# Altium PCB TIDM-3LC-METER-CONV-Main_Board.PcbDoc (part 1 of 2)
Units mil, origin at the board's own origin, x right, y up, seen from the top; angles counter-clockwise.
Board outline 4050 x 4800 mil, 4 copper layers (Top Layer, Mid-Layer 1, Mid-Layer 2, Bottom Layer); 180 components, 206 nets, 819 pads, 257 vias.
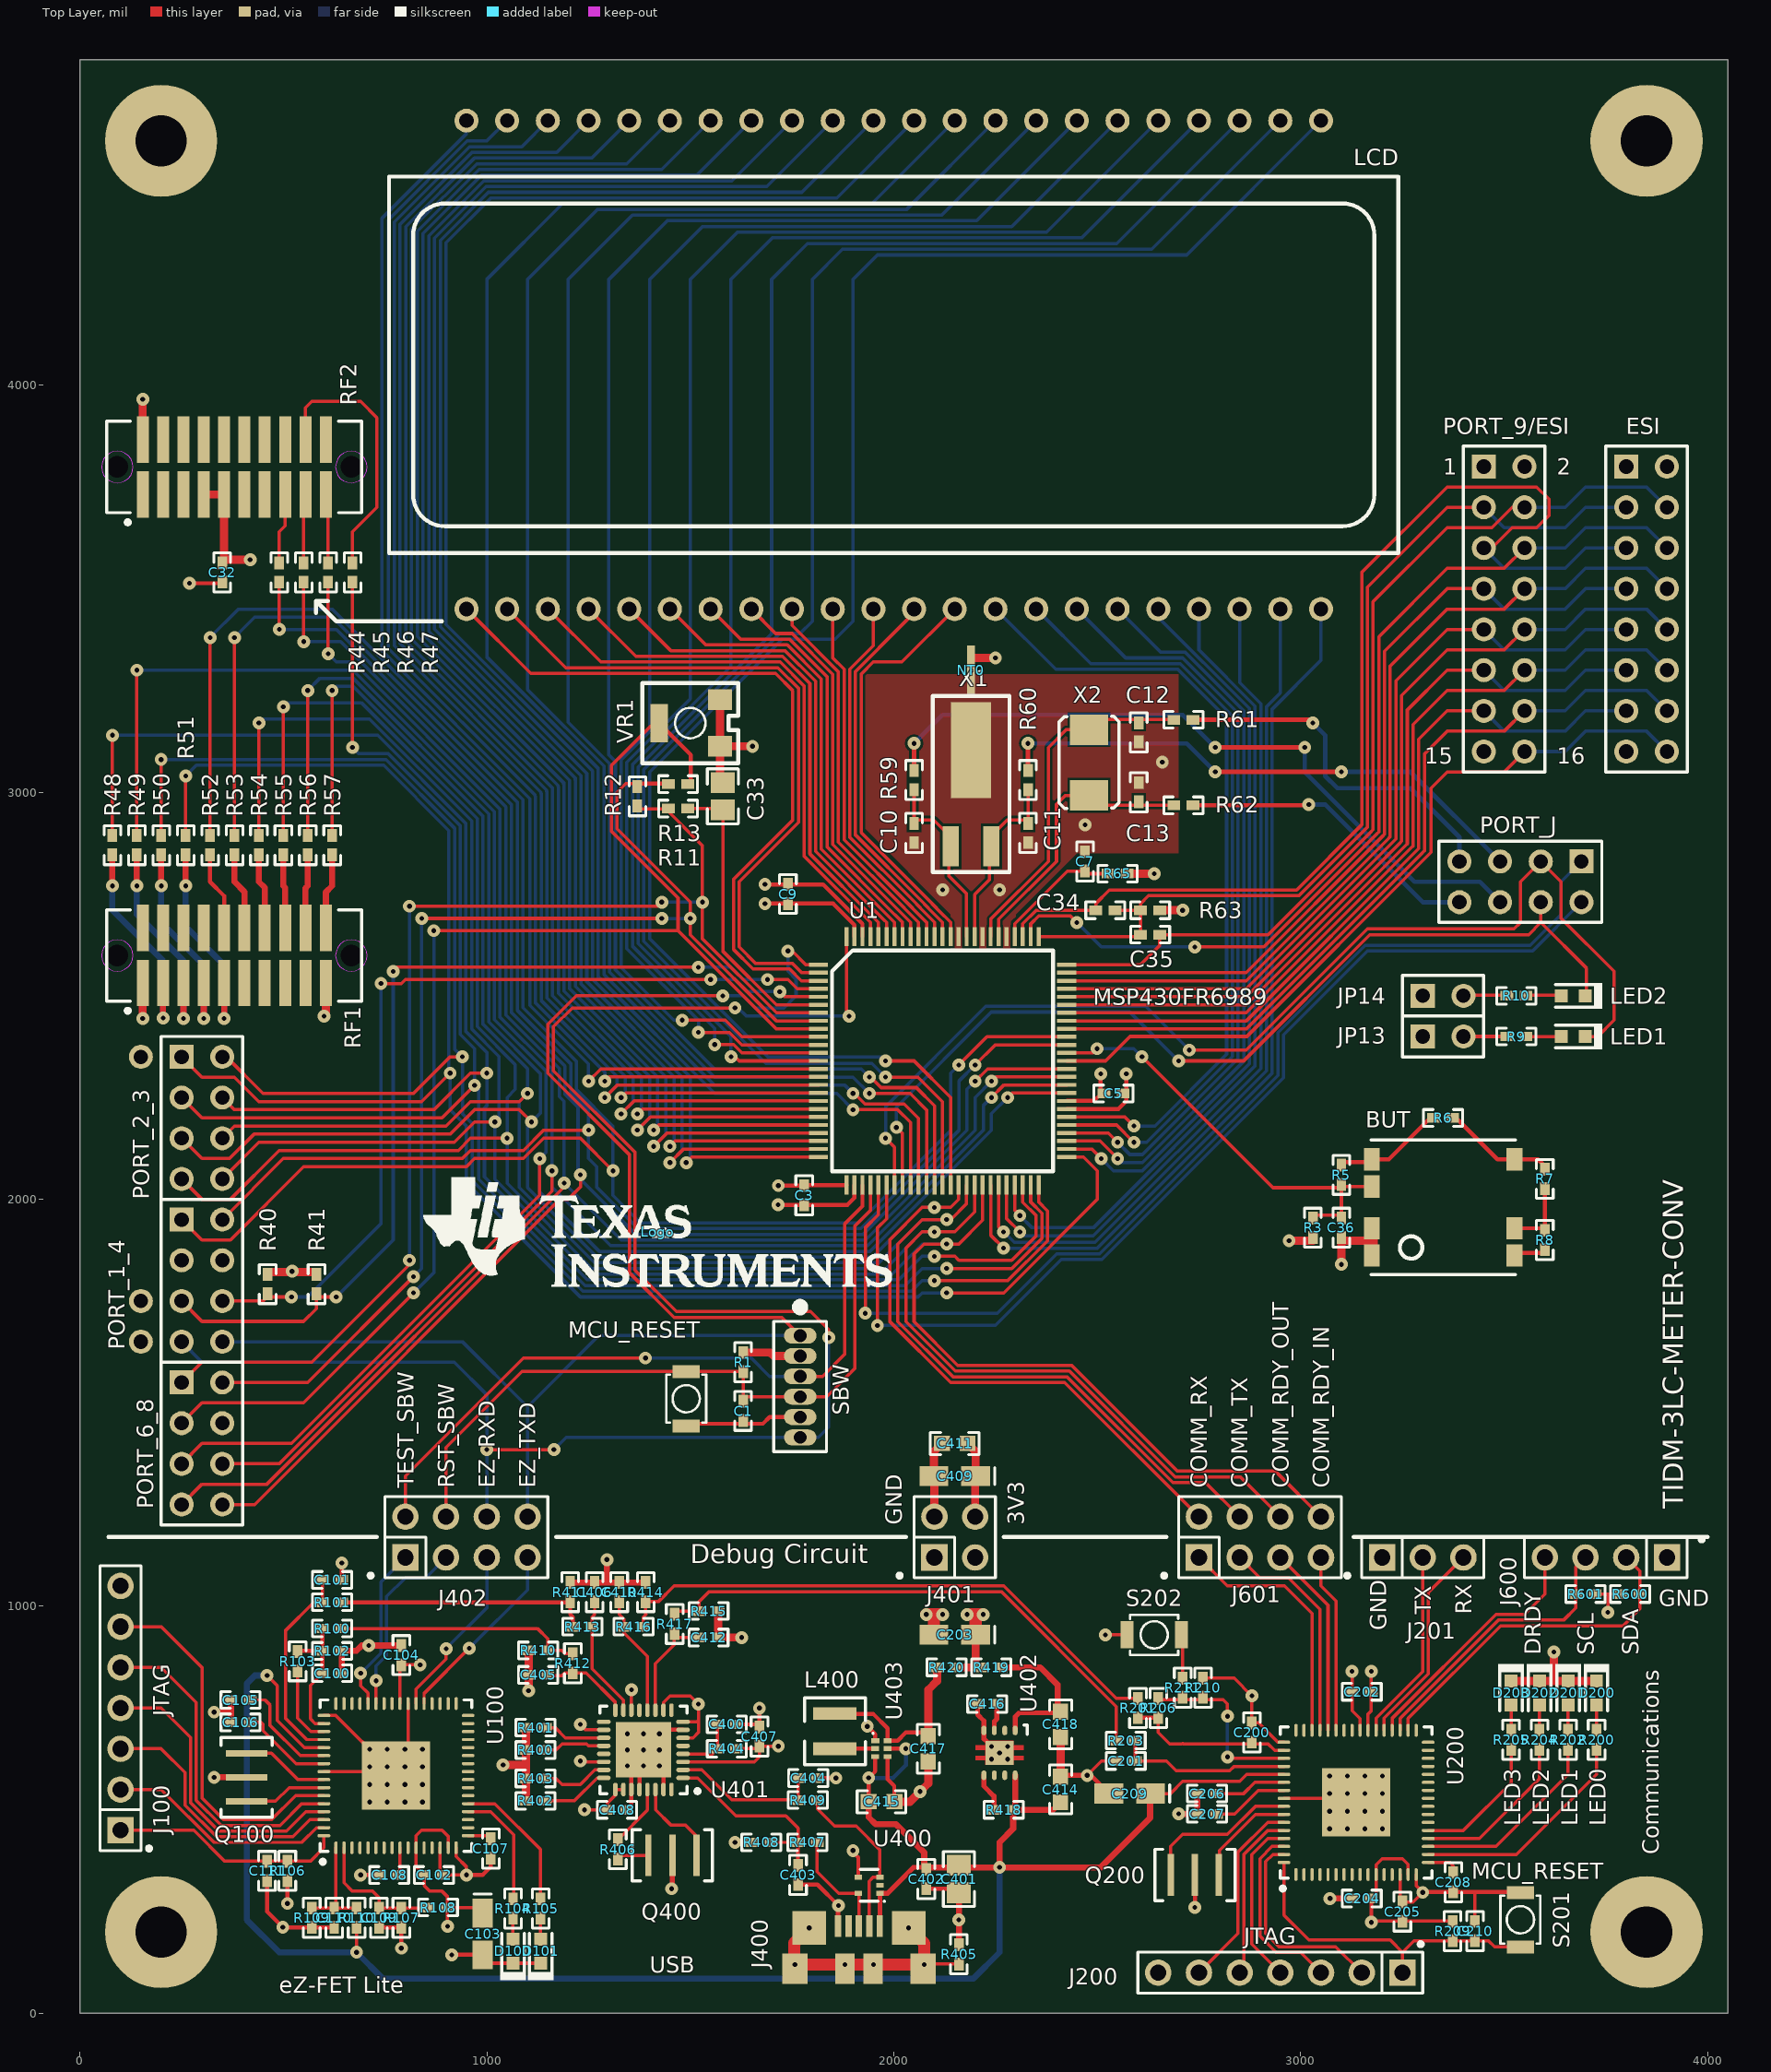
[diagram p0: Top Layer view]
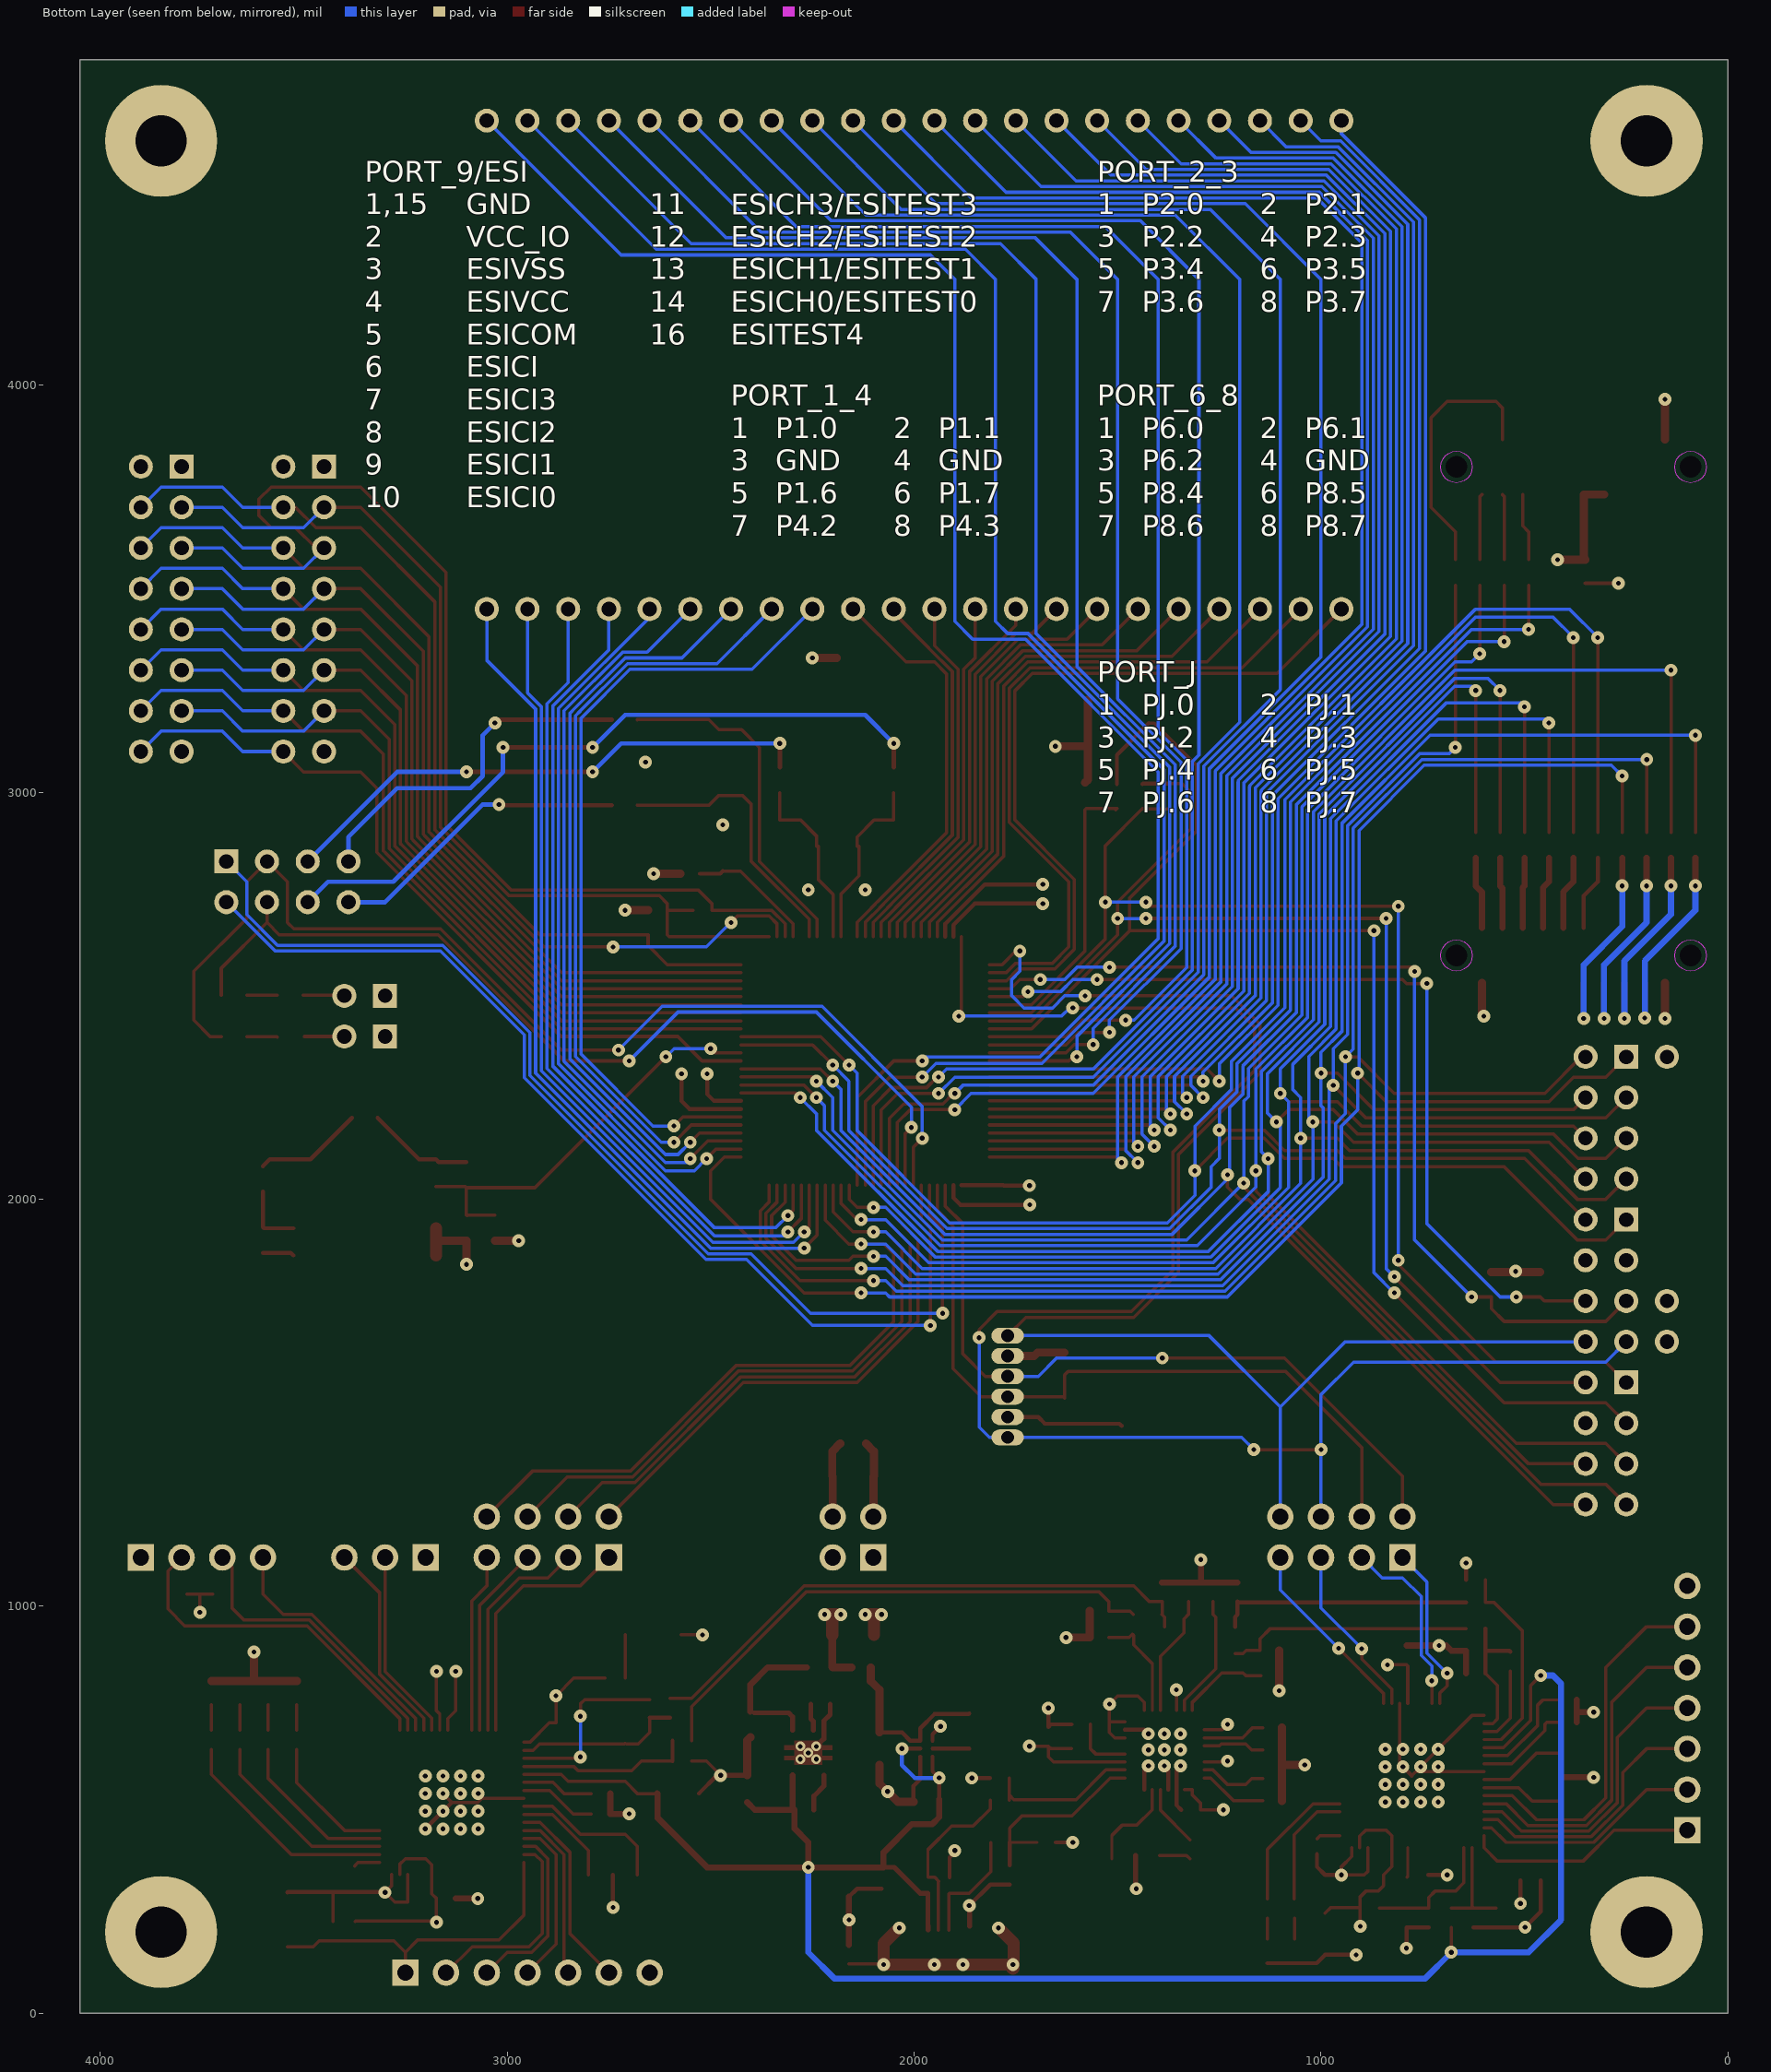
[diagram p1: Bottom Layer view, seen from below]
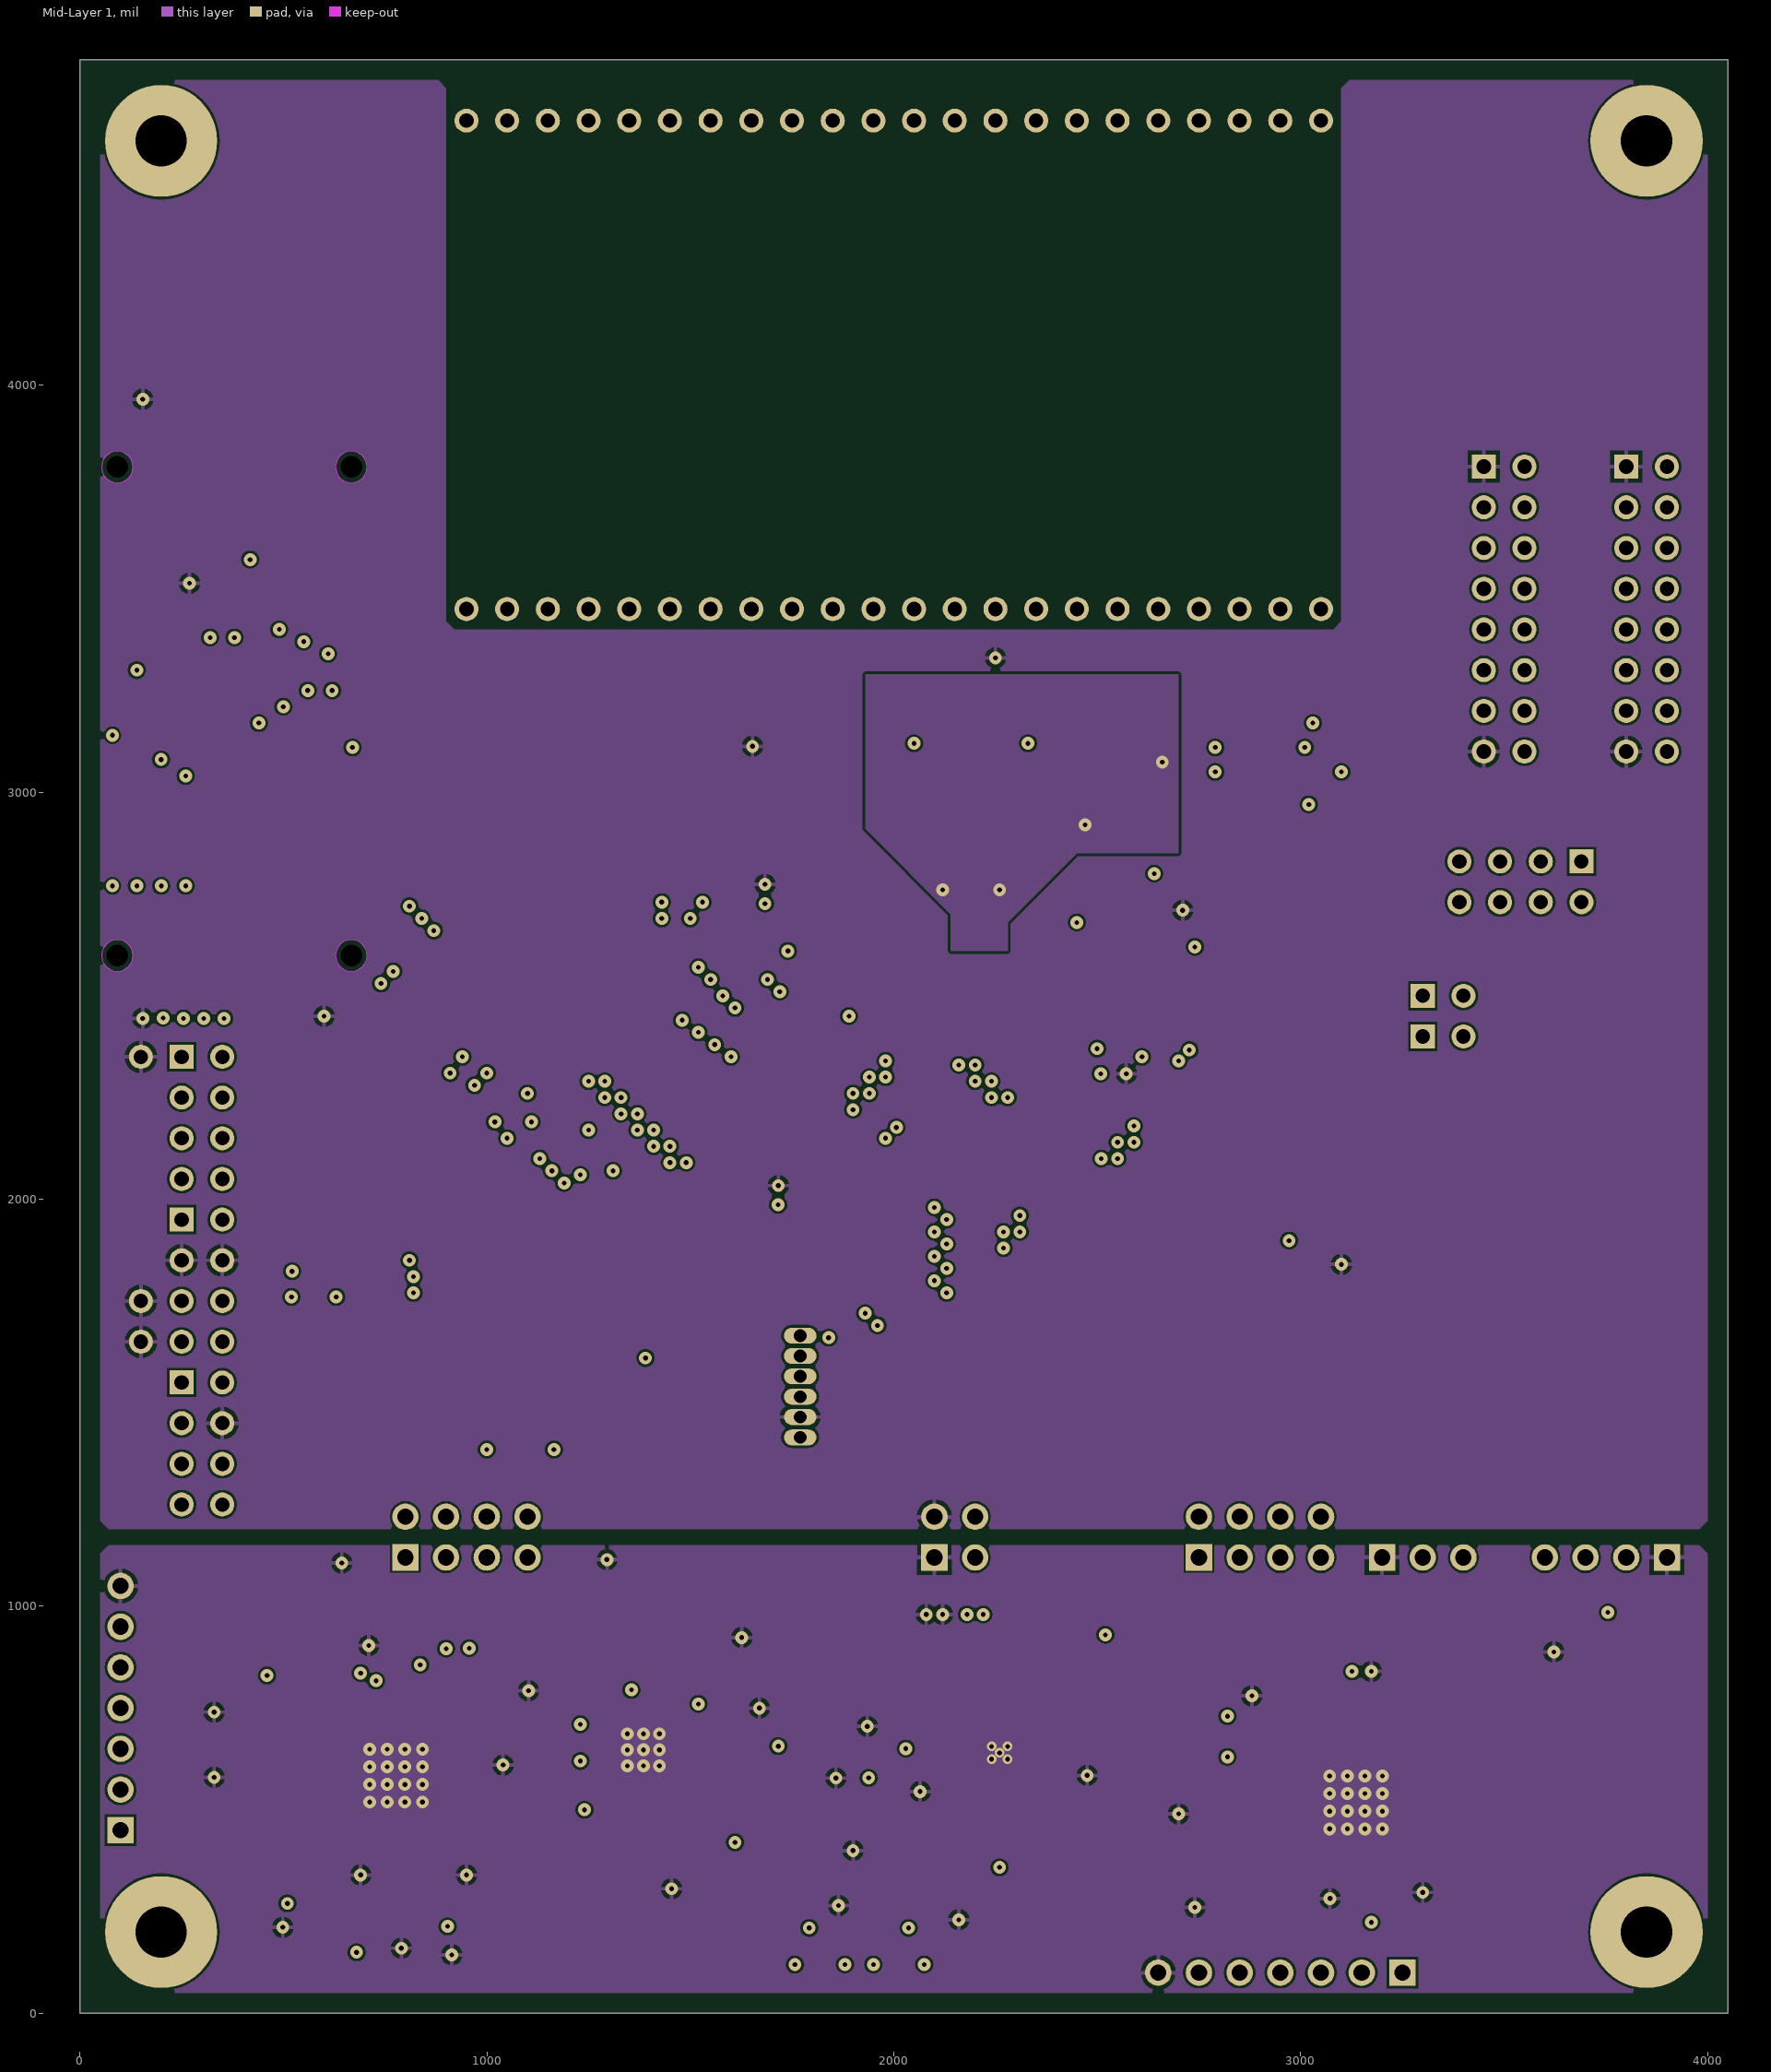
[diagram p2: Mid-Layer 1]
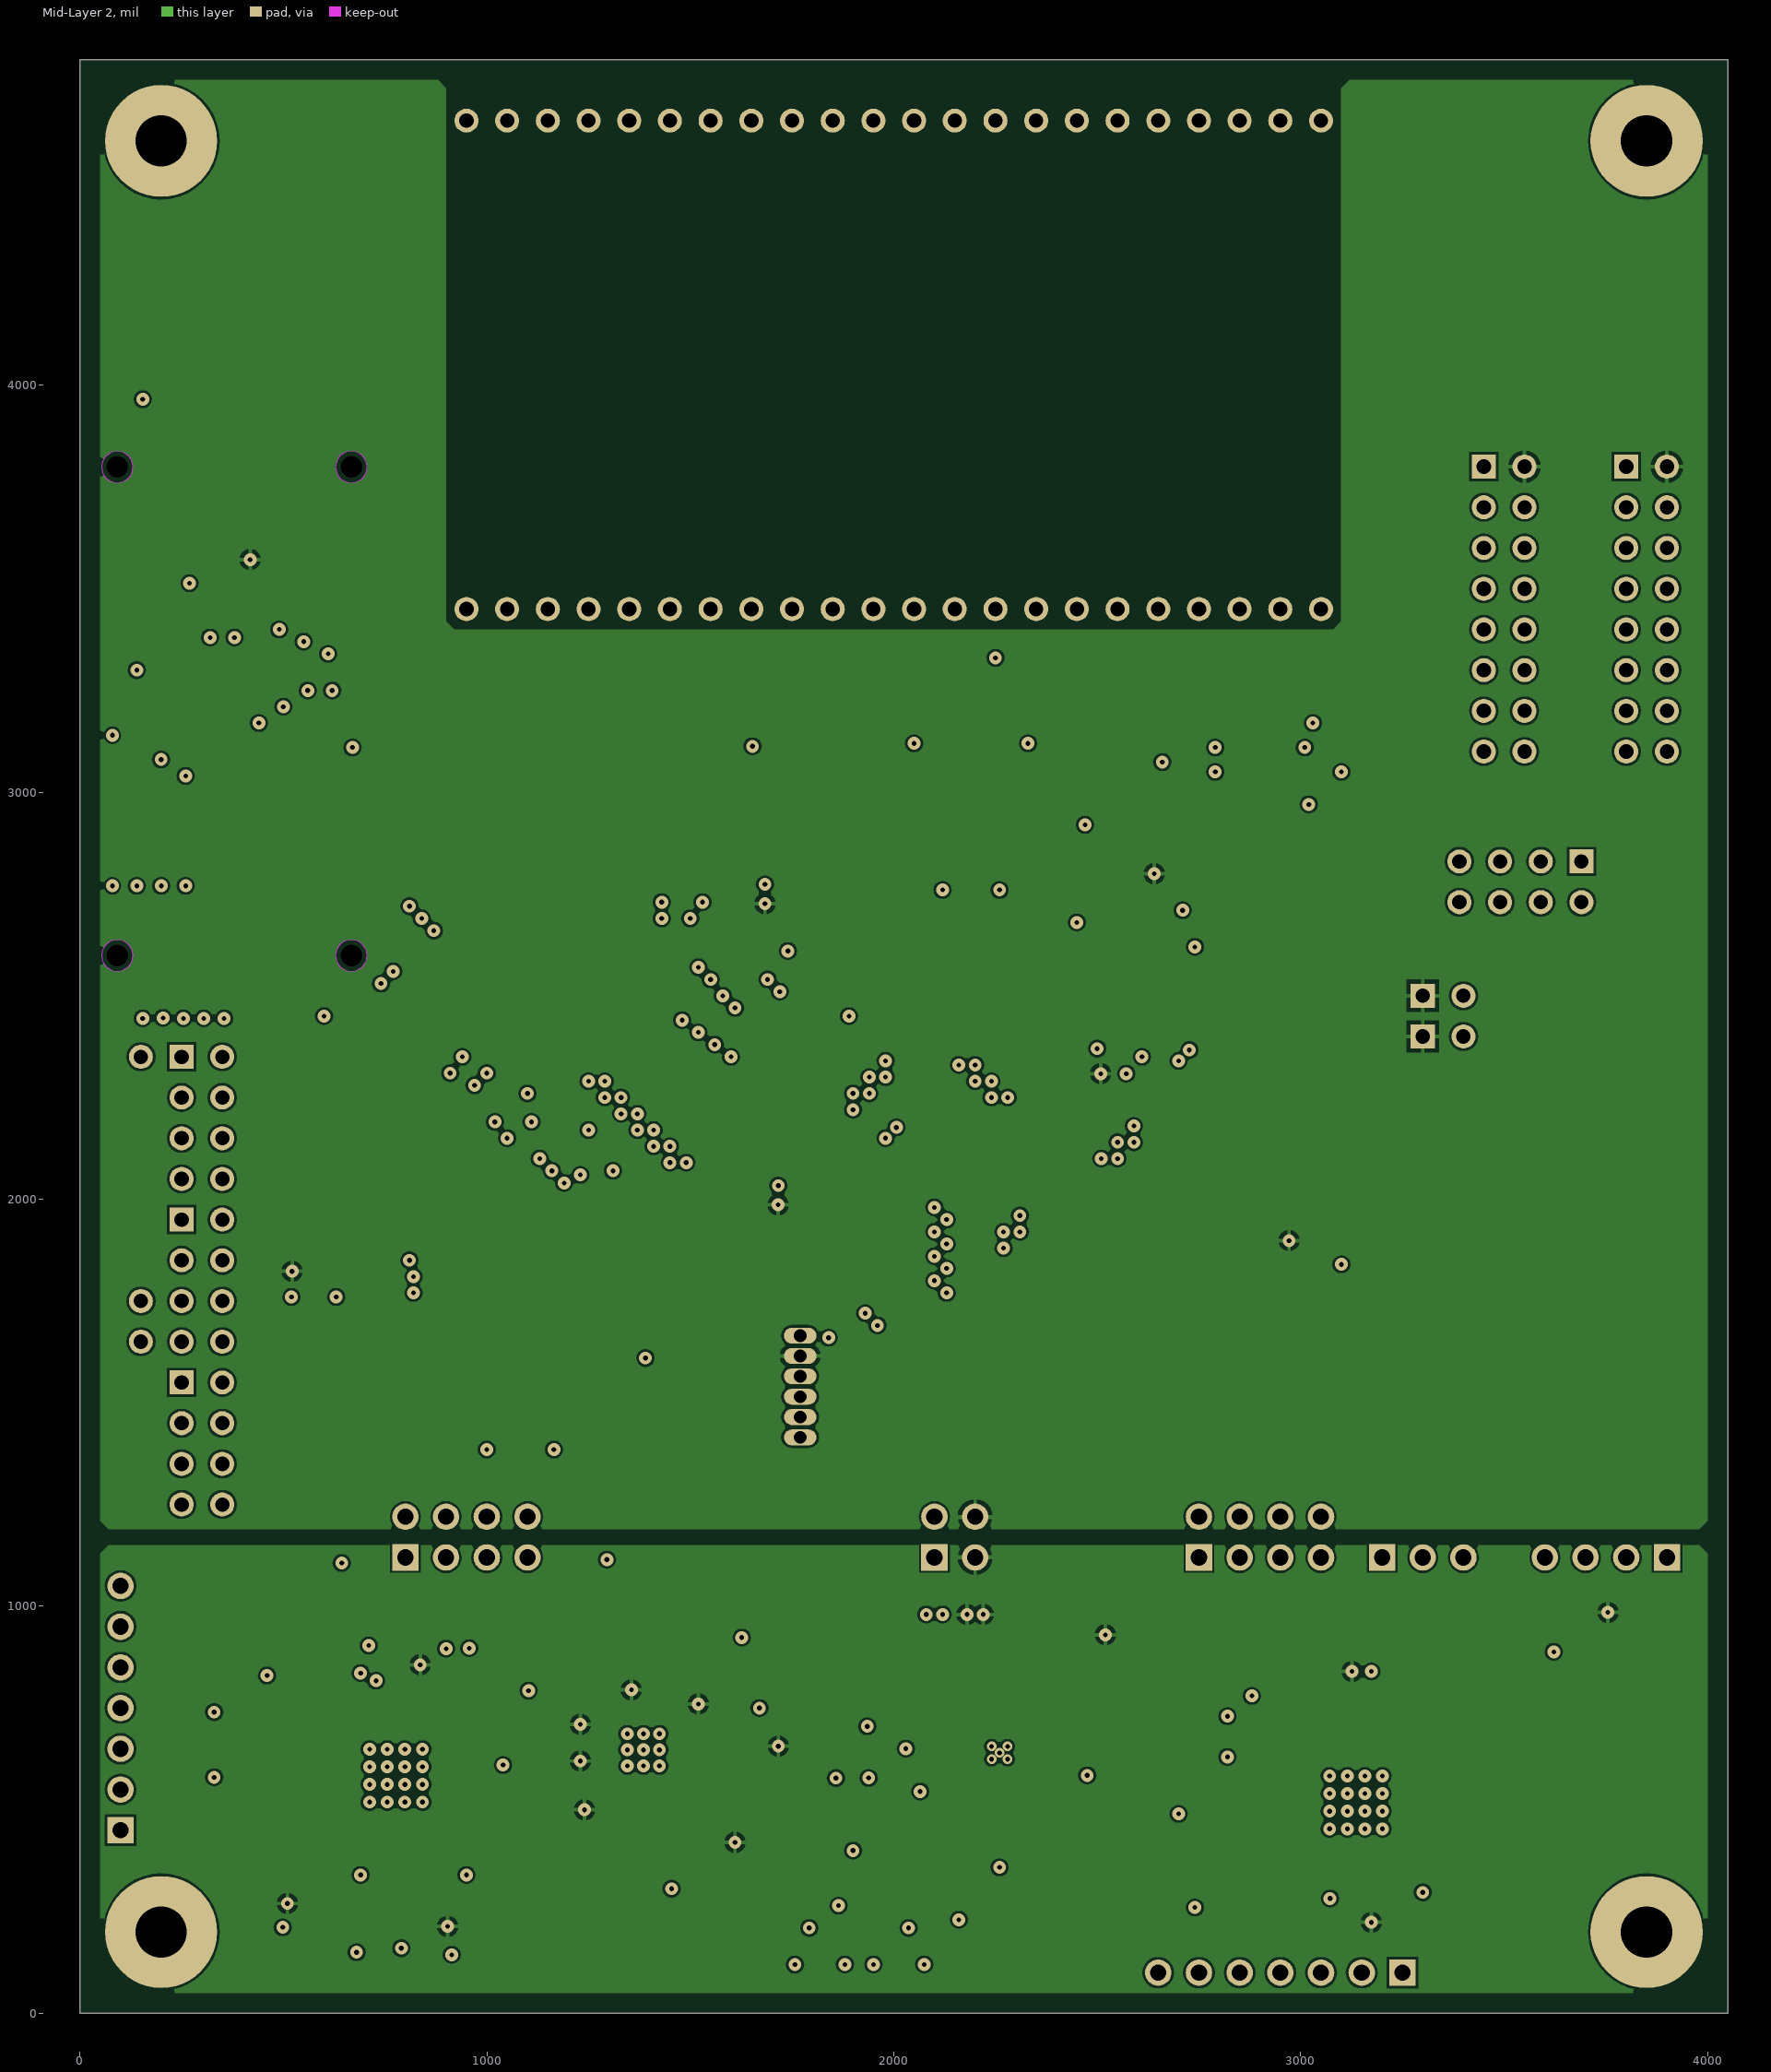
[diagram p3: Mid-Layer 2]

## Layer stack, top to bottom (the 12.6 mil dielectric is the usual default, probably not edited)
Top Layer: signal copper 1.4
Dielectric: core 12.6, FR-4, Dk 4.8
Mid-Layer 1: signal copper 1.4
Dielectric: prepreg 12.6, FR-4, Dk 4.8
Mid-Layer 2: signal copper 1.4
Dielectric: core 12.6, FR-4, Dk 4.8
Bottom Layer: signal copper 1.4

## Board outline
0,0 0,4800 4050,4800 4050,0

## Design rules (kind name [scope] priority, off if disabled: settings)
AcuteAngle [All] p1: minimum=4.50000000000000E+0001 checktracksonly=FALSE
AssemblyTestPointUsage [All] p1: valid=2
Clearance [All] p1: gap=6
Clearance Clearance_1 [InNet('AGND')] p2: gap=10
ComponentClearance ComponentClearance_Logo [All] p1 off: gap=50 collisioncheckmode=3 verticalgap=10 showdistances=FALSE
ComponentClearance ComponentClearance_ScrewToNut [(HasFootprint('NY PMS 440 0025 PH')) vs (HasFootprint('Keystone_1902C'))] p2 off: gap=5 collisioncheckmode=3 verticalgap=10 showdistances=FALSE
ComponentClearance ComponentClearance_MountingHoles [InComponentClass('Mounting Holes')] p3 off: gap=250 collisioncheckmode=3 verticalgap=100000 showdistances=FALSE
ComponentClearance ComponentClearance_SmallPassives [HasFootprint('0201*') or HasFootprint('0402*') or HasFootprint('0508') or HasFootprint('0603*') or HasFootprint('0612') or HasFootprint('0805*') or HasFootprint('0815*') or HasFootprint('0830*') or HasFootprint('1206*') or HasFootprint('1210*') or HasFootprint('1808*') or HasFootprint('1812*') or HasFootprint('1825*') or HasFootprint('2010*') or HasFootprint('2220*') or HasFootprint('2225*') or HasFootprint('2512*') or HasFootprint('2728*') or HasFootprint('3518*') vs HasFootprint('0201*') or HasFootprint('0402*') or HasFootprint('0508') or HasFootprint('0603*') or HasFootprint('0612') or HasFootprint('0805*') or HasFootprint('0815*') or HasFootprint('0830*') or HasFootprint('1206*') or HasFootprint('1210*') or HasFootprint('1808*') or HasFootprint('1812*') or HasFootprint('1825*') or HasFootprint('2010*') or HasFootprint('2220*') or HasFootprint('2225*') or HasFootprint('2512*') or HasFootprint('2728*') or HasFootprint('3518*')] p4 off: gap=20 collisioncheckmode=3 verticalgap=10 showdistances=FALSE
ComponentClearance ComponentClearance_THtoSMT [IsThruComponent vs IsSMTComponent] p5 off: gap=100 collisioncheckmode=3 verticalgap=100000 showdistances=FALSE
ComponentClearance ComponentClearance_THtoTH [IsThruComponent vs IsThruComponent] p6 off: gap=118.11 collisioncheckmode=3 verticalgap=100000 showdistances=FALSE
ComponentClearance [All] p7 off: gap=40 collisioncheckmode=3 verticalgap=10 showdistances=FALSE
DiffPairsRouting [All] p1: maxlimit=100 minlimit=10 mostfreqgap=10 maxuncoupledlength=1000
FabricationTestPointUsage TestPointUsage [All] p1: valid=2 allowmultiple=FALSE
FabricationTestpoint Testpoint [All] p1: side=3 testpointundercomponent=TRUE minsize=40 maxsize=100 preferedsize=60 minholesize=0 maxholesize=40 preferedholesize=32 testpointgrid=1 allowsidetop=TRUE allowsidebottom=TRUE usegrid=TRUE gridtolerance=0.01
FanoutControl Fanout_LCC [IsLCC] p1: bgadir=Out bgaviamode=Centered fanoutstyle=Auto fanoutdirection=Alternating viagrid=1 // Fanout_LCC (Default Rule)
FanoutControl Fanout_BGA [IsBGA] p2: bgadir=Out bgaviamode=Centered fanoutstyle=Auto fanoutdirection=Alternating viagrid=1 // Fanout_BGA (Default Rule)
FanoutControl Fanout_Default [All] p4: bgadir=Out bgaviamode=Centered fanoutstyle=Auto fanoutdirection=Alternating viagrid=1 // Fanout_Default (Default Rule)
FanoutControl Fanout_Small [(CompPinCount < 5)] p5: bgadir=Out bgaviamode=Centered fanoutstyle=Auto fanoutdirection=OutThenIn viagrid=1 // Fanout_Small (Default Rule)
HoleSize [All] p1: absolutevalues=TRUE maxlimit=248.03 minlimit=11.81 maxpercent=80.000 minpercent=20.000
MinimumAnnularRing [All] p1: minimumring=6
MinimumSolderMaskSliver MinimumSolderMaskSliver_Logo [InComponentClass('Logo') vs InComponentClass('Logo')] p1: minsoldermaskwidth=0.7
MinimumSolderMaskSliver [All] p2: minsoldermaskwidth=1
PlaneConnect PlaneConnect_1 [All] p1: planeconnectstyle=Relief reliefexpansion=10 reliefentries=4 reliefconductorwidth=10 reliefairgap=10
PolygonConnect PolygonConnect_5 [All vs IsNamedPolygon('Mid-Layer 1-No Net 4')] p1: connectstyle=Direct reliefconductorwidth=10 reliefentries=4 polygonreliefangle="90 Angle" airgapwidth=10
PolygonConnect PolygonConnect_4 [All vs IsNamedPolygon('Mid-Layer 1-No Net 3')] p2: connectstyle=Direct reliefconductorwidth=10 reliefentries=4 polygonreliefangle="90 Angle" airgapwidth=10
PolygonConnect PolygonConnect_3 [All vs IsNamedPolygon('Mid-Layer 1-No Net 2')] p3: connectstyle=Direct reliefconductorwidth=10 reliefentries=4 polygonreliefangle="90 Angle" airgapwidth=10
PolygonConnect PolygonConnect_2 [All vs IsNamedPolygon('Mid-Layer 1-No Net 1')] p4: connectstyle=Direct reliefconductorwidth=10 reliefentries=4 polygonreliefangle="90 Angle" airgapwidth=10
PolygonConnect [InNet('AGND')] p5: connectstyle=Direct reliefconductorwidth=10 reliefentries=4 polygonreliefangle="90 Angle" airgapwidth=10
PolygonConnect PolygonConnect_1 [All] p6: connectstyle=Relief reliefconductorwidth=10 reliefentries=4 polygonreliefangle="90 Angle" airgapwidth=10
RoutingVias [All] p1: holewidth=11.81 width=31.5 viastyle="Through Hole" minholewidth=11.81 minwidth=31.5 maxholewidth=31.5 maxwidth=59.06
SilkToSilkClearance [All] p1: silktosilkclearance=5
SilkscreenOverComponentPads [All] p1: minsilkscreentomaskgap=5
SolderMaskExpansion [All] p1: expansion=3
Width [All] p1: maxlimit=30 minlimit=6 preferedwidth=8
14 further rules are at their usual default settings.

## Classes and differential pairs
component class MCU: BUT C1 C3 C5 C7 C9 C10 C11 C12 C13 C32 C33 C34 C35 C36 ESI JP13 JP14 LCD LED1 LED2 LFXT Logo MCU_RESET NT0 PORT_1_4 PORT_2_3 PORT_6_8 PORT_9/ESI PORT_J R1 R3 R5 R6 R7 R8 R9 R10 R11 R12 R13 R40 R41 R44 R45 R46 R47 R48 R49 R50 R51 R52 R53 R54 R55 R56 R57 R59 R60 R61 R62 R63 R65 RF1 RF2 SBW U1 VR1 X1 X2
component class ezFET_lite_sch: C100 C101 C102 C103 C104 C105 C106 C107 C108 C109 C110 C111 C409 C411 D100 D101 J100 J401 J402 Q100 R100 R101 R102 R103 R104 R105 R106 R107 R108 R109 R110 U100
component class Header: J100 J200 J201 J401 J402 J600 J601
component class usb_hub_and_power_sch: C400 C401 C402 C403 C404 C405 C406 C407 C408 C410 C412 C414 C415 C416 C417 C418 J400 L400 Q400 R400 R401 R402 R403 R404 R405 R406 R407 R408 R409 R410 R411 R412 R413 R414 R415 R416 R417 R418 R419 R420 U400 U401 U402 U403
component class usb_mcu_bridge_sch: C200 C201 C202 C203 C204 C205 C206 C207 C208 C209 C210 D200 D201 D202 D203 J200 J201 J600 J601 Q200 R200 R201 R202 R203 R204 R205 R206 R209 R210 R211 R600 R601 S201 S202 U200
component class Logo: Logo

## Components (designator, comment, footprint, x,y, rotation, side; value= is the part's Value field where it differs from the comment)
BUT "Used in BOM report" TPA511GLFS 3350,1980 r0 top
C1 "" 0402 1630,1480 r90 top
C3 "" 0402 1780,2010 r270 top
C5 "" 0402 2540,2260 r0 top
C7 "" 0402 2470,2830 r270 top
C9 "" 0402 1740,2750 r270 top
C10 "" 0402 2050,2900 r90 top
C11 "" 0402 2330,2900 r270 top
C12 "" 0402 2602,3147 r90 top
C13 "" 0402 2602,3000 r90 top
C32 "" 0402 350,3540 r270 top
C33 "" 0805 1580,2990 r270 top
C34 "" 0402 2520,2710 r0 top
C35 "" 0402 2630,2650 r0 top
C36 "" 0402 3100,1930 r270 top
C100 "500R07S100JV4T" 0402 620,835.5 r0 top
C101 "500R07S100JV4T" 0402 620,1065 r0 top
C102 "C1005X5R1A104K" 0402 870,340 r0 top
C103 "TPSA106M010R1800" 3216-18 990,195 r270 top
C104 "C1005X5R1A104K" 0402 790,880 r90 top
C105 "GRM155R61A224KE19D" 0402 395,770 r180 top
C106 "GRM155R61A224KE19D" 0402 395,715 r180 top
C107 "GRM155R61A474KE15D" 0402 1010,405 r270 top
C108 "C1005X5R1A104K" 0402 760,340 r180 top
C109 "GRM1555C1H330JA01D" 0402 735,235 r270 top
C110 "GRM1555C1H330JA01D" 0402 625,235 r270 top
C111 "C1005X7R1H102K" 0402 460,350 r270 top
C200 "GRM1555C1H100JA01D" 0402 2880,690 r90 top
C201 "GRM1555C1H100JA01D" 0402 2570,620 r180 top
C202 "GRM155R61C104KA88D" 0402 3150,790 r0 top
C203 "TPSA106M010R1800" 3216-18 2150,930 r180 top
C204 "GRM155R61C104KA88D" 0402 3150,282.16 r180 top
C205 "GRM155R61C104KA88D" 0402 3250,250 r90 top
C206 "GRM155R61A224KE19D" 0402 2770,540 r180 top
C207 "GRM155R61A224KE19D" 0402 2770,490 r180 top
C208 "GRM155R61A474KE15D" 0402 3375,322.16 r270 top
C209 "293D106X0010A2TE3" 3216-18 2580,540 r180 top
C210 "C1005X7R1H102K" 0402 3428.19,202.16 r90 top
C400 "GRM155R61C104KA88D" 0402 1590,710 r0 top
C401 "293D475X9010A2TE3" 0805 2160,330 r270 top
C402 "GRM155R61C104KA88D" 0402 2080,330 r270 top
C403 "GRM1555C1H220JA01D" 0402 1765,340 r270 top
C404 "GRM1555C1H220JA01D" 0402 1790,578 r0 top
C405 "GRM1555C1H100JA01D" 0402 1126.31,831.65 r180 top
C406 "GRM1555C1H100JA01D" 0402 1265,1035 r90 top
C407 "GRM155R61C104KA88D" 0402 1670,680 r90 top
C408 "GRM155R61C104KA88D" 0402 1320,500 r0 top
C409 "TPSA106M010R1800" 3216-18 2150,1320 r180 top
C410 "GRM1555C1H100JA01D" 0402 1325.5,1035 r90 top
C411 "C1608X7R1C105K" 0603 2150,1400 r180 top
C412 "GRM1555C1H100JA01D" 0402 1545,923.35 r0 top
C414 "C0603C105K8PACTU" 0603 2410,550 r90 top
C415 "GRM21BR71A105KA01L" 0603 1970,520 r0 top
C416 "GRM155R61C103KA01D" 0402 2230,760 r180 top
C417 "GRM21BR71A105KA01L" 0603 2085,650 r270 top
C418 "C0603C225K8PACTU" 0603 2410,710 r270 top
D100 "LTST-C190CKT" LED_LTST-C190_Red 1064.44,152.69 r270 top
D101 "LTST-C190GKT" LED_LTST-C190 1132.16,152.69 r270 top
D200 "LTST-C190CKT" LED_LTST-C190_Red 3727,787.16 r90 top
D201 "LTST-C190GKT" LED_LTST-C190 3657,787.16 r90 top
D202 "LTST-C190GKT" LED_LTST-C190 3587,787.16 r90 top
D203 "LTST-C190GKT" LED_LTST-C190 3517,787.16 r90 top
ESI "MHDR2X8" HDR2X8 3800,3800 r270 top
J100 "TSW-107-07-G-S" TSW-107-07-G-S 100,750 r90 top
J200 "TSW-107-07-G-S" TSW-107-07-G-S 2950,100 r180 top
J201 "TSW-103-07-G-S" TSW-103-07-G-S 3300,1120 r0 top
J400 "ZX62R-B-5P" CONN_USB_micro_ZX62R-B-5PA 1914.45,214.68 r0 top
J401 "TSW-102-07-G-D" TSW-102-07-G-D 2150,1170 r0 top
J402 "TSW-104-07-G-D" TSW-104-07-G-D 950,1170 r0 top
J600 "TSW-104-07-G-S" TSW-104-07-G-S 3750,1120 r180 top
J601 "TSW-104-07-G-D" TSW-104-07-G-D 2900,1170 r0 top
JP13 "JUMPER" HDR1X2 3300,2400 r0 top
JP14 "JUMPER" HDR1X2 3300,2500 r0 top
L400 "NR3010T2R2M" INDUCTOR_2.2UH_SMD 1855,650 r90 top
LCD "FH-1152P" FH-1152P 2000,4050 r0 top locked
LED1 "" LED_LTST-C190 3670,2400 r0 top
LED2 "" LED_LTST-C190 3670,2500 r0 top
Logo "Texas Instruments" TI_Stacked_Overlay_Medium 1420,1920 r0 top
MCU_RESET "" B3U-1000P 1490,1510 r90 top
NT0 "Net-Tie" Net-Tie_20milWide_60milLong 2190,3300 r90 top net-tie
PORT_1_4 "MHDR2X4" HDR2X4 250,1950 r270 top
PORT_2_3 "MHDR2X4" HDR2X4 250,2350 r270 top
PORT_6_8 "MHDR2X4" HDR2X4 250,1550 r270 top
PORT_9/ESI "MHDR2X8" HDR2X8 3450,3800 r270 top (schematic designator ESI2)
PORT_J "MHDR2X4" HDR2X4 3690,2830 r180 top
Q100 "MURATA-FILTER_CSTCR4M00G15" "CSTCR CERAMIC RESONATOR - MURATA" 410,580 r270 top
Q200 "MURATA-FILTER_CSTCR4M00G15" "CSTCR CERAMIC RESONATOR - MURATA" 2740,340 r0 top
Q400 "CSTCR4M00G15L99" "CSTCR CERAMIC RESONATOR - MURATA" 1456,388 r180 top
R1 "" 0402 1630,1600 r90 top
R3 "" 0402 3030,1930 r270 top
R5 "" 0402 3100,2060 r270 top
R6 "" 0402 3350,2200 r180 top
R7 "" 0402 3600,2050 r90 top
R8 "" 0402 3600,1900 r90 top
R9 "" 0402 3530,2400 r0 top
R10 "" 0402 3530,2500 r0 top
R11 "" 0402 1470,2960 r0 top
R12 "" 0402 1370,2990 r270 top
R13 "" 0402 1470,3020 r180 top
R40 "" 0402 461.49,1791.49 r90 top
R41 "" 0402 581.49,1791.49 r90 top
R44 "" 0402 490,3540 r270 top
R45 "" 0402 550,3540 r270 top
R46 "" 0402 610,3540 r270 top
R47 "" 0402 670,3540 r270 top
R48 "" 0402 80,2870 r90 top
R49 "" 0402 140,2870 r90 top
R50 "" 0402 200,2870 r90 top
R51 "" 0402 260,2870 r90 top
R52 "" 0402 320,2870 r90 top
R53 "" 0402 380,2870 r90 top
R54 "" 0402 440,2870 r90 top
R55 "" 0402 500,2870 r90 top
R56 "" 0402 560,2870 r90 top
R57 "" 0402 620,2870 r90 top
R59 "" 0402 2050,3030 r90 top
R60 "" 0402 2330,3030 r90 top
R61 "" 0402 2712,3178 r180 top
R62 "" 0402 2712,2968 r180 top
R63 "" 0402 2630,2710 r180 top
R65 "" 0402 2550,2800 r0 top
R100 "CRCW040227R0JNED" 0402 620,945.5 r180 top
R101 "CRCW040227R0JNED" 0402 620,1010 r180 top
R102 "CRCW04021M00JNED" 0402 620,890.5 r0 top
R103 "CRCW04021K30JNED" 0402 535,865 r90 top
R104 "CRCW0402470RJNED" 0402 1064.44,257.69 r90 top
R105 "CRCW0402390RJNED" 0402 1132.16,257.69 r90 top
R106 "CRCW040247K0JNED" 0402 510,350 r270 top
R107 "CRCW0402220KJNED" 0402 790,235 r90 top
R108 "CRCW0402220KJNED" 0402 880,260 r0 top
R109 "CRCW0402150KFKED" 0402 570,235 r90 top
R110 "CRCW0402240KJNED" 0402 680,235 r270 top
R200 "CRCW0402470RJNED" 0402 3727,672.16 r270 top
R201 "CRCW040227R0JNED" 0402 2600,750 r270 top
R202 "CRCW0402390RJNED" 0402 3657,672.16 r270 top
R203 "CRCW040227R0JNED" 0402 2570,670 r0 top
R204 "CRCW0402390RJNED" 0402 3587,672.16 r270 top
R205 "CRCW0402390RJNED" 0402 3517,672.16 r270 top
R206 "CRCW04021K40FKED" 0402 2650,750 r90 top
R209 "CRCW040247K0JNED" 0402 3373.19,202.16 r90 top
R210 "CRCW04021M00JNED" 0402 2760,800 r270 top
R211 "CRCW0402100RJNED" 0402 2710,800 r90 top
R400 "CRCW040215K0FKED" 0402 1119.84,646.97 r0 top
R401 "CRCW040215K0FKED" 0402 1119.84,701.97 r0 top
R402 "CRCW040215K0FKED" 0402 1119.84,521.97 r0 top
R403 "CRCW040215K0FKED" 0402 1119.84,576.97 r0 top
R404 "CRCW040247K0JNED" 0402 1590,650 r0 top
R405 "CRCW040233R0JNED" 0402 2160,145 r90 top
R406 "CRCW040227R0JNED" 0402 1322,403 r90 top
R407 "CRCW040222R0JNED" 0402 1788.19,420 r180 top
R408 "CRCW04021K50JNED" 0402 1675,420 r180 top
R409 "CRCW040222R0JNED" 0402 1789.19,524 r180 top
R410 "CRCW040215K0FKED" 0402 1126.31,891.65 r0 top
R411 "CRCW040215K0FKED" 0402 1205,1035 r270 top
R412 "CRCW040222R0JNED" 0402 1211.31,860 r270 top
R413 "CRCW040222R0JNED" 0402 1235,950 r0 top
R414 "CRCW040215K0FKED" 0402 1390.5,1035 r270 top
R415 "CRCW040215K0FKED" 0402 1545,988.35 r180 top
R416 "CRCW040222R0JNED" 0402 1360.5,950 r180 top
R417 "CRCW040222R0JNED" 0402 1461.65,956.81 r270 top
R418 "CRCW040210K0JNED" 0402 2270,500 r180 top
R419 "CRCW040222R0JNED" 0402 2240,850 r0 top
R420 "CRCW040222R0JNED" 0402 2130,850 r180 top
R600 "CRCW04024K70JNED" 0402 3810,1030 r0 top
R601 "CRCW04024K70JNED" 0402 3700,1030 r180 top
RF1 "MHDR2X10" TFM-110-02-SM-D-A-K 379.5,2599 r0 top
RF2 "MHDR2X10" TFM-110-02-SM-D-A-K 379.5,3799 r0 top locked
S201 "" B3U-1000P 3540,230 r270 top
S202 "" B3U-1000P 2640,930 r180 top
SBW "Header 6" CONN_SMS-106-01-G-S 1770,1540 r90 top
U1 "MSP430FR6989" MSP430FR6989 2120,2340 r270 top
U100 "MSP430F5528IRGCR" TI_RGC0064B_N 777,584 r90 top
U200 "MSP430F5528IRGCT" TI_RGC0064B_N 3136.08,518.24 r90 top
U400 "TPD2E001DRLR" DRL0005A 1939.45,314.68 r180 top
U401 "TUSB2046BIRHBR" RHB0032E 1384.84,647.28 r180 top
U402 "TPS73533DRB (DNP)" DRB0008A 2260,640 r270 top
U403 "TPS62237DRYR" DRY0006A 1969.84,650.32 r0 top
VR1 "" VR-3150 1500,3170 r90 top
X1 "32.768" 01-CR3-1B 2190,3020 r270 top
X2 "DNP" ABM3 2480,3073 r90 top

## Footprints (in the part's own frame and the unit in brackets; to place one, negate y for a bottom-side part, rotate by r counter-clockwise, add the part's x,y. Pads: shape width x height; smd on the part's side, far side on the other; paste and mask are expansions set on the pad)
01-CR3-1B [mm]
  rect 2.5x1 smd: 1(3.875,-1.27) 2(3.875,1.27)
  rect 6x2.5 smd: 3(-2.125,0)
  silkscreen extent -5.5,-2.4 5.5,2.4
0402 [mm] "0402 from SM-752 data"
  rect 0.8x0.6 smd: 1(-0.6,0) 2(0.6,0)
  silkscreen extent -1.22,-0.52 1.22,0.52, body extent -0.55,-0.3 0.55,0.3, height 0.6
0603 [mm] "0603 from SM-752 data"
  rect 1x0.95 smd: 1(-0.8,0) 2(0.8,0)
  silkscreen extent -1.52,-0.69 1.52,0.69, body extent -0.87,-0.47 0.87,0.47, height 0.85
0805 [mm] "0805 from SM-752 data"
  rect 1.3x1.5 smd: 1(-0.85,0) 2(0.85,0)
  silkscreen extent -1.72,-0.97 1.72,0.97, body extent -1.1,-0.72 1.1,0.72, height 1.1
3216-18 [mm] "Medium density IPC, based on Kemet T495 dimensions"
  rect 1.8x1.25 smd: 1(-1.3,0) 2(1.3,0)
  silkscreen extent -2.49,-0.54 -2.49,0.54, body extent -1.7,-0.9 1.7,0.9, height 1.8
ABM3 [mm]
  rect 1.9x2.4 smd: 1(2.05,0) 2(-2.05,0)
  silkscreen extent -2.86,-1.87 2.89,1.87
B3U-1000P [mm]
  rect 0.8x1.7 smd: 1(-1.7,0) 2(1.7,0)
  silkscreen extent -1.5,-1.25 1.5,1.25
CONN_SMS-106-01-G-S [mil] "SAMTEC"
  oval 39x80 hole 31 mask+3: 1(125,0) 2(75,0) 3(25,0) 4(-25,0) 5(-75,0) 6(-125,0)
  silkscreen extent -160,-65 205,65, body extent -158,-62 158,62, height 341
CONN_USB_micro_ZX62R-B-5PA [mm] "Hirose"
  rect 0.4x1.35 smd: 1(1.3,0) 2(0.65,0) 3(0,0) 4(-0.65,0) 5(-1.3,0)
  rect 1.2x1.9 smd: 6(-0.875,-2.675) 7(0.875,-2.675)
  rect 1.6x1.9 smd: 8(-4,-2.675) 9(4,-2.675)
  rect 2.1x2.1 smd: 10(-3.1,-0.125) 11(3.1,-0.125)
  body extent -3.75,-5.33 3.75,0.18, height 2.55
"CSTCR CERAMIC RESONATOR - MURATA" [mm] "CSTCR-Resonator SMD footprint"
  rect 0.4x2.6 smd: 1(-1.5,0) 2(0,0) 3(1.5,0)
  silkscreen extent -2.49,-1.6 2.5,1.6, body extent -2.25,-1 2.25,1, height 1.1
DRB0008A [mm] "SON, 8-Leads, Body 3x3mm, Pitch 0.65mm, Thermal Pad 1.75x1.5mm, TI Recommended"
  oval 0.6x0.3 smd: 1(-1.4,0.975) 2(-1.4,0.325) 3(-1.4,-0.325) 4(-1.4,-0.975) 5(1.4,-0.975) 6(1.4,-0.325) 7(1.4,0.325) 8(1.4,0.975)
  rect 1.5x1.75 smd paste-0.75: 9(0,0)
  Top Layer region: -0.465,-1.5 -0.465,-0.875 -0.75,-0.875 -0.75,0.875 -0.465,0.875 -0.465,1.5 -0.185,1.5 -0.185,0.875 0.185,0.875 0.185,1.5 0.465,1.5 0.465,0.875 0.75,0.875 0.75,-0.875 0.465,-0.875 0.465,-1.5 0.185,-1.5 0.185,-0.875 -0.185,-0.875 -0.185,-1.5
  silkscreen extent -1.72,1.53 -1.15,1.73, body extent -1.57,-1.57 1.58,1.58, height 1.01
DRL0005A [mm] "SOTFL, 5-Flat Leads, Body 1.2x1.6x0.6mm, Pitch 0.5mm, TI Recommended"
  rect 0.45x0.3 smd: 1(-0.675,0.5) 2(-0.675,0) 3(-0.675,-0.5) 4(0.675,-0.5) 5(0.675,0.5)
  silkscreen extent -1,-1 0.55,1.05, body extent -0.65,-0.85 0.65,0.85, height 0.6
DRY0006A [mm] "PSON, 6-Leads, Body 1x1.45mm, Pitch 0.5mm, TI Recommended"
  rect 0.52x0.3 smd paste+0 mask+0.05: 1(-0.385,0.5)
  rect 0.49x0.3 smd paste+0 mask+0.05: 2(-0.385,0) 3(-0.385,-0.5) 4(0.385,-0.5) 5(0.385,0) 6(0.385,0.5)
  silkscreen extent -0.57,0.9 -0.48,1, body extent -0.53,-0.75 0.53,0.75, height 0.6
FH-1152P [mm]
  round 1.5 hole 0.9: 1(-26.67,-15.24) 2(-24.13,-15.24) 3(-21.59,-15.24) 4(-19.05,-15.24) 5(-16.51,-15.24) 6(-13.97,-15.24) 7(-11.43,-15.24) 8(-8.89,-15.24) 9(-6.35,-15.24) 10(-3.81,-15.24) 11(-1.27,-15.24) 12(1.27,-15.24) 13(3.81,-15.24) 14(6.35,-15.24) 15(8.89,-15.24) 16(11.43,-15.24) 17(13.97,-15.24) 18(16.51,-15.24) 19(19.05,-15.24) 20(21.59,-15.24) 21(24.13,-15.24) 22(26.67,-15.24) 23(26.67,15.24) 24(24.13,15.24) 25(21.59,15.24) 26(19.05,15.24) 27(16.51,15.24) 28(13.97,15.24) 29(11.43,15.24) 30(8.89,15.24) 31(6.35,15.24) 32(3.81,15.24) 33(1.27,15.24) 34(-1.27,15.24) 35(-3.81,15.24) 36(-6.35,15.24) 37(-8.89,15.24) 38(-11.43,15.24) 39(-13.97,15.24) 40(-16.51,15.24) 41(-19.05,15.24) 42(-21.59,15.24) 43(-24.13,15.24) 44(-26.67,15.24)
  silkscreen extent -31.5,-11.75 31.5,11.75
HDR1X2 [mm] "Connector; Header; 2 Position"
  rect 1.5x1.5 hole 0.9: 1(0,0)
  round 1.5 hole 0.9: 2(2.54,0)
  silkscreen extent -1.27,-1.27 3.81,1.27
HDR2X4 [mm] "Connector; Header; 4x2 Position"
  rect 1.5x1.5 hole 0.9: 1(0,0)
  round 1.5 hole 0.9: 2(0,2.54) 3(2.54,0) 4(2.54,2.54) 5(5.08,0) 6(5.08,2.54) 7(7.62,0) 8(7.62,2.54)
  silkscreen extent -1.27,-1.27 8.89,3.81
HDR2X8 [mm] "Connector; Header; 8x2 Position"
  rect 1.5x1.5 hole 0.9: 1(0,0)
  round 1.5 hole 0.9: 2(0,2.54) 3(2.54,0) 4(2.54,2.54) 5(5.08,0) 6(5.08,2.54) 7(7.62,0) 8(7.62,2.54) 9(10.16,0) 10(10.16,2.54) 11(12.7,0) 12(12.7,2.54) 13(15.24,0) 14(15.24,2.54) 15(17.78,0) 16(17.78,2.54)
  silkscreen extent -1.27,-1.27 19.05,3.81
INDUCTOR_2.2UH_SMD [mm] "Inductor, 2.2uH, 1A, 3x3mm, SMD footprint"
  rect 0.8x2.7 smd: 1(0,0) 2(2.2,0)
  silkscreen extent -0.99,-1.91 3.17,1.88, body extent -0.65,-1.6 2.85,1.6, height 1
LED_LTST-C190 [mm] "Lite-On"
  rect 0.8x0.8 smd: 1(-0.75,0) 2(0.75,0)
  silkscreen extent -1.1,-0.8 1.8,0.8, body extent -0.85,-0.45 0.85,0.45, height 0.9
LED_LTST-C190_Red [mm] "Lite-On"
  rect 0.8x0.8 smd: 1(-0.75,0) 2(0.75,0)
  silkscreen extent -1.1,-0.8 1.8,0.8, body extent -0.85,-0.45 0.85,0.45, height 0.9
MSP430FR6989 [mm]
  rect 0.25x1.2 smd: 1(-6,-7.75) 2(-5.5,-7.75) 3(-5,-7.75) 4(-4.5,-7.75) 5(-4,-7.75) 6(-3.5,-7.75) 7(-3,-7.75) 8(-2.5,-7.75) 9(-2,-7.75) 10(-1.5,-7.75) 11(-1,-7.75) 12(-0.5,-7.75) 13(0,-7.75) 14(0.5,-7.75) 15(1,-7.75) 16(1.5,-7.75) 17(2,-7.75) 18(2.5,-7.75) 19(3,-7.75) 20(3.5,-7.75) 21(4,-7.75) 22(4.5,-7.75) 23(5,-7.75) 24(5.5,-7.75) 25(6,-7.75) 51(6,7.75) 52(5.5,7.75) 53(5,7.75) 54(4.5,7.75) 55(4,7.75) 56(3.5,7.75) 57(3,7.75) 58(2.5,7.75) 59(2,7.75) 60(1.5,7.75) 61(1,7.75) 62(0.5,7.75) 63(0,7.75) 64(-0.5,7.75) 65(-1,7.75) 66(-1.5,7.75) 67(-2,7.75) 68(-2.5,7.75) 69(-3,7.75) 70(-3.5,7.75) 71(-4,7.75) 72(-4.5,7.75) 73(-5,7.75) 74(-5.5,7.75) 75(-6,7.75)
  rect 1.2x0.25 smd: 26(7.75,-6) 27(7.75,-5.5) 28(7.75,-5) 29(7.75,-4.5) 30(7.75,-4) 31(7.75,-3.5) 32(7.75,-3) 33(7.75,-2.5) 34(7.75,-2) 35(7.75,-1.5) 36(7.75,-1) 37(7.75,-0.5) 38(7.75,0) 39(7.75,0.5) 40(7.75,1) 41(7.75,1.5) 42(7.75,2) 43(7.75,2.5) 44(7.75,3) 45(7.75,3.5) 46(7.75,4) 47(7.75,4.5) 48(7.75,5) 49(7.75,5.5) 50(7.75,6) 76(-7.75,6) 77(-7.75,5.5) 78(-7.75,5) 79(-7.75,4.5) 80(-7.75,4) 81(-7.75,3.5) 82(-7.75,3) 83(-7.75,2.5) 84(-7.75,2) 85(-7.75,1.5) 86(-7.75,1) 87(-7.75,0.5) 88(-7.75,0) 89(-7.75,-0.5) 90(-7.75,-1) 91(-7.75,-1.5) 92(-7.75,-2) 93(-7.75,-2.5) 94(-7.75,-3) 95(-7.75,-3.5) 96(-7.75,-4) 97(-7.75,-4.5) 98(-7.75,-5) 99(-7.75,-5.5) 100(-7.75,-6)
  round 1.5 on Top Overlay: 47(-7.5,-7.5)
  silkscreen extent -6.9,-6.9 6.9,6.9
Net-Tie_20milWide_60milLong [mil] "20mil net tie, no solder mask opening, no solder paste"
  rect 60x20 smd paste-10 mask-10: 1(-30,0) 2(30,0)
RHB0032E [mm] "QFN, 32-Leads, Body 5x5mm, Pitch 0.5mm, Thermal Pad 3.45x3.45mm, TI Recommended"
  oval 0.85x0.28 smd paste-0.025 mask+0.07: 1(-2.475,1.75) 2(-2.475,1.25) 3(-2.475,0.75) 4(-2.475,0.25) 5(-2.475,-0.25) 6(-2.475,-0.75) 7(-2.475,-1.25) 8(-2.475,-1.75) 17(2.475,-1.75) 18(2.475,-1.25) 19(2.475,-0.75) 20(2.475,-0.25) 21(2.475,0.25) 22(2.475,0.75) 23(2.475,1.25) 24(2.475,1.75)
  oval 0.28x0.85 smd paste-0.025 mask+0.07: 9(-1.75,-2.475) 10(-1.25,-2.475) 11(-0.75,-2.475) 12(-0.25,-2.475) 13(0.25,-2.475) 14(0.75,-2.475) 15(1.25,-2.475) 16(1.75,-2.475) 25(1.75,2.475) 26(1.25,2.475) 27(0.75,2.475) 28(0.25,2.475) 29(-0.25,2.475) 30(-0.75,2.475) 31(-1.25,2.475) 32(-1.75,2.475)
  rect 3.45x3.45 smd paste-1.725 mask+0.07: 33(0,0)
  silkscreen extent -3.5,-2.72 2.73,2.73, body extent -2.57,-2.57 2.58,2.58, height 1
TFM-110-02-SM-D-A-K [mm]
  rect 0.75x2.9 smd mask+0: 1(-5.715,-1.715) 2(-5.715,1.714) 3(-4.445,-1.715) 4(-4.445,1.714) 5(-3.175,-1.715) 6(-3.175,1.714) 7(-1.905,-1.715) 8(-1.905,1.714) 9(-0.635,-1.715) 10(-0.635,1.714) 11(0.635,-1.715) 12(0.635,1.714) 13(1.905,-1.715) 14(1.905,1.714) 15(3.175,-1.715) 16(3.175,1.714) 17(4.445,-1.715) 18(4.445,1.714) 19(5.715,-1.715) 20(5.715,1.714)
  round 1 hole 1.35 unplated mask+0: 21(-7.303,0) 22(7.302,0)
  Keep-Out Layer pour cut-out: 8.286,0 8.253,0.255 8.154,0.492 7.998,0.695 7.794,0.852 7.557,0.95 7.303,0.983 7.048,0.95 6.811,0.852 6.607,0.695 6.451,0.492 6.353,0.255 6.319,0 6.353,-0.255 6.451,-0.492 6.607,-0.695 6.811,-0.852 7.048,-0.95 7.303,-0.983 7.557,-0.95 7.794,-0.852 7.998,-0.695 8.154,-0.492 8.253,-0.255
  Keep-Out Layer pour cut-out: -6.319,0 -6.353,0.255 -6.451,0.492 -6.607,0.695 -6.811,0.852 -7.048,0.95 -7.303,0.983 -7.557,0.95 -7.794,0.852 -7.998,0.695 -8.154,0.492 -8.253,0.255 -8.286,0 -8.253,-0.255 -8.154,-0.492 -7.998,-0.695 -7.794,-0.852 -7.557,-0.95 -7.303,-0.983 -7.048,-0.95 -6.811,-0.852 -6.607,-0.695 -6.451,-0.492 -6.353,-0.255
  silkscreen extent -7.95,-3.57 7.95,2.85
TI_RGC0064B_N [mm] "QFN, 64-Leads, Body 9x9mm, Pitch 0.5mm, Thermal Pad 4.25x4.25mm, IPC Medium Density"
  oval 0.8x0.2 smd: 1(-4.5,3.75) 2(-4.5,3.25) 3(-4.5,2.75) 4(-4.5,2.25) 5(-4.5,1.75) 6(-4.5,1.25) 7(-4.5,0.75) 8(-4.5,0.25) 9(-4.5,-0.25) 10(-4.5,-0.75) 11(-4.5,-1.25) 12(-4.5,-1.75) 13(-4.5,-2.25) 14(-4.5,-2.75) 15(-4.5,-3.25) 16(-4.5,-3.75) 33(4.5,-3.75) 34(4.5,-3.25) 35(4.5,-2.75) 36(4.5,-2.25) 37(4.5,-1.75) 38(4.5,-1.25) 39(4.5,-0.75) 40(4.5,-0.25) 41(4.5,0.25) 42(4.5,0.75) 43(4.5,1.25) 44(4.5,1.75) 45(4.5,2.25) 46(4.5,2.75) 47(4.5,3.25) 48(4.5,3.75)
  oval 0.2x0.8 smd: 17(-3.75,-4.5) 18(-3.25,-4.5) 19(-2.75,-4.5) 20(-2.25,-4.5) 21(-1.75,-4.5) 22(-1.25,-4.5) 23(-0.75,-4.5) 24(-0.25,-4.5) 25(0.25,-4.5) 26(0.75,-4.5) 27(1.25,-4.5) 28(1.75,-4.5) 29(2.25,-4.5) 30(2.75,-4.5) 31(3.25,-4.5) 32(3.75,-4.5) 49(3.75,4.5) 50(3.25,4.5) 51(2.75,4.5) 52(2.25,4.5) 53(1.75,4.5) 54(1.25,4.5) 55(0.75,4.5) 56(0.25,4.5) 57(-0.25,4.5) 58(-0.75,4.5) 59(-1.25,4.5) 60(-1.75,4.5) 61(-2.25,4.5) 62(-2.75,4.5) 63(-3.25,4.5) 64(-3.75,4.5)
  rect 4.25x4.25 smd: 65(0,0)
  silkscreen extent -5.5,-4.72 4.72,4.73, body extent -4.58,-4.57 4.57,4.58, height 1
TI_Stacked_Overlay_Medium [mil]
  silkscreen extent -576,-136 576,134
TPA511GLFS [mm]
  rect 1x1.4 smd: 1(-4.45,-3) 2(-4.45,-1.3) 3(4.45,-1.3) 4(4.45,-3) 5(4.45,3) 6(-4.45,1.3) 7(-4.45,3)
  silkscreen extent -4.5,-4.2 4.5,4.2
TSW-102-07-G-D [mm] "Samtec 100mil, 2x2, 230 mil above insulator"
  rect 1.65x1.65 hole 1.016 mask+0: 1(-1.27,-1.27)
  round 1.65 hole 1.016 mask+0: 2(-1.27,1.27) 3(1.27,-1.27) 4(1.27,1.27)
  silkscreen extent -3.56,-2.54 2.54,2.54, body extent -2.54,-2.54 2.54,2.54, height 8.38
TSW-103-07-G-S [mm] "Samtec 100mil, 1x3, 230 mil above insulator"
  rect 1.65x1.65 hole 1.016 mask+0: 1(-2.54,0)
  round 1.65 hole 1.016 mask+0: 2(0,0) 3(2.54,0)
  silkscreen extent -4.83,-1.27 3.81,1.27, body extent -3.81,-1.27 3.81,1.27, height 8.38
TSW-104-07-G-D [mm] "Samtec 100mil, 2x4, 230 mil above insulator"
  rect 1.65x1.65 hole 1.016 mask+0: 1(-3.81,-1.27)
  round 1.65 hole 1.016 mask+0: 2(-3.81,1.27) 3(-1.27,-1.27) 4(-1.27,1.27) 5(1.27,-1.27) 6(1.27,1.27) 7(3.81,-1.27) 8(3.81,1.27)
  silkscreen extent -6.1,-2.54 5.08,2.54, body extent -5.08,-2.54 5.08,2.54, height 8.38
TSW-104-07-G-S [mm] "Samtec 100mil, 1x4, 230 mil above insulator"
  rect 1.65x1.65 hole 1.016 mask+0: 1(-3.81,0)
  round 1.65 hole 1.016 mask+0: 2(-1.27,0) 3(1.27,0) 4(3.81,0)
  silkscreen extent -6.11,-1.27 5.08,1.27, body extent -5.08,-1.27 5.08,1.27, height 8.38
TSW-107-07-G-S [mm] "Samtec 100mil, 1x7, 230 mil above insulator (modified silk - moved #1 dot)"
  rect 1.65x1.65 hole 1.016 mask+0: 1(-7.62,0)
  round 1.65 hole 1.016 mask+0: 2(-5.08,0) 3(-2.54,0) 4(0,0) 5(2.54,0) 6(5.08,0) 7(7.62,0)
  silkscreen extent -8.89,-1.9 8.89,1.27, body extent -8.89,-1.27 8.89,1.27, height 8.38
VR-3150 [mm]
  rect 1.3x1.5 smd: 1(1.45,-1.85) 3(-1.45,-1.85)
  rect 2.4x1.1 smd: 2(0,1.95)
  silkscreen extent -2.5,-3 2.5,3

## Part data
BUT: library part "Nav Button"
C1 C3 C5 C7 C9 C10 C11 C12 C13 C32 C33 C34 C35 C36: library part Cap, "Capacitor"
C100 C101 C200 C201 C405 C406 C410 C412: "CAP, CERM, 10pF, 50V, +/-5%, C0G/NP0, 0402"
C102 C104 C108: "CAP, CERM, 0.1uF, 10V, +/-10%, X5R, 0402"
C103 C203 C409: "CAP, TA, 10uF, 10V, +/-20%, 1.8 ohm, SMD"
C105 C106 C206 C207: "CAP, CERM, 0.22uF, 10V, +/-10%, X5R, 0402"
C107 C208: "CAP, CERM, 0.47uF, 10V, +/-10%, X5R, 0402"
C109 C110: "CAP, CERM, 33pF, 50V, +/-5%, C0G/NP0, 0402"
C111 C210: "CAP, CERM, 1000pF, 50V, +/-10%, X7R, 0402"
C202 C204 C205 C400 C402 C407 C408: "CAP, CERM, 0.1uF, 16V, +/-10%, X5R, 0402"
C209: "CAP, TA, 10uF, 10V, +/-20%, 3.4 ohm, SMD"
C401: "CAP, TA, 4.7uF, 10V, +/-10%, 5 ohm, SMD"
C403 C404: "CAP, CERM, 22pF, 50V, +/-5%, C0G/NP0, 0402"
C411: "CAP, CERM, 1uF, 16V, +/-10%, X7R, 0603"
C414: "CAP, CERM, 1uF, 10V, +/-10%, X5R, 0603"
C415 C417: "CAP, CERM, 1uF, 10V, +/-10%, X7R, 0805"
C416: "CAP, CERM, 0.01uF, 16V, +/-10%, X5R, 0402"
C418: "CAP, CERM, 2.2uF, 10V, +/-10%, X5R, 0603"
D100 D200: "LED, Red, SMD"
D101 D201 D202 D203: "LED, Green, SMD"
ESI PORT_9/ESI: "Header, 8-Pin, Dual row"
J100 J200: "Header, TH, 100mil, 7x1, Gold plated, (modified silk pin #1)"
J201: "Header, TH, 100mil, 3x1, Gold plated, 230 mil above insulator"
J400: "Connector, micro USB Type B, Reverse, Receptacle, SMD"
J401: "Header, TH, 100mil, 2x2, Gold plated, 230 mil above insulator"
J402 J601: "Header, TH, 100mil, 4x2, Gold plated, 230 mil above insulator"
J600: "Header, TH, 100mil, 4x1, Gold plated, 230 mil above insulator"
L400: "Inductor, 2.2uH, 20%, 1.1A,, 0.095 ohm, SMD"
LED1 LED2: library part LED2, "Typical RED, GREEN, YELLOW, AMBER GaAs LED"
Logo: library part TI_Logo, "Texas Instrument Corporate Signature"
MCU_RESET S201 S202: library part SW-PB, "Switch"
NT0: "Single point connection between nets."
PORT_1_4 PORT_2_3 PORT_6_8 PORT_J: "Header, 4-Pin, Dual row"
Q400: library part MURATA-FILTER_CSTCR6M00G15
R1 R3 R5 R6 R7 R8 R9 R10 R11 R12 R13 R40 R41 R44 R45 R46 R47 R48 R49 R50 R51 R52 R53 R54 R55 R56 R57 R59 R60 R61 R62 R63 R65: library part Res2, "Resistor"
R100 R101 R201 R203 R406: "RES, 27 ohm, 5%, 0.063W, 0402"
R102 R210: "RES, 1.0Meg ohm, 5%, 0.063W, 0402"
R103: "RES, 1.3k ohm, 5%, 0.063W, 0402"
R104 R200: "RES, 470 ohm, 5%, 0.063W, 0402"
R105 R202 R204 R205: "RES, 390 ohm, 5%, 0.063W, 0402"
R106 R209 R404: "RES, 47k ohm, 5%, 0.063W, 0402"
R107 R108: "RES, 220k ohm, 5%, 0.063W, 0402"
R109: "RES, 150k ohm, 1%, 0.063W, 0402"
R110: "RES, 240k ohm, 5%, 0.063W, 0402"
R206: "RES, 1.40k ohm, 1%, 0.063W, 0402"
R211: "RES, 100 ohm, 5%, 0.063W, 0402"
R400 R401 R402 R403 R410 R411 R414 R415: "RES, 15.0k ohm, 1%, 0.063W, 0402"
R405: "RES, 33 ohm, 5%, 0.063W, 0402"
R407 R409 R412 R413 R416 R417 R419 R420: "RES, 22 ohm, 5%, 0.063W, 0402"
R408: "RES, 1.5k ohm, 5%, 0.063W, 0402"
R418: "RES, 10k ohm, 5%, 0.063W, 0402"
R600 R601: "RES, 4.7k ohm, 5%, 0.063W, 0402"
RF1 RF2: "Header, 10-Pin, Dual row"
SBW: "Header, 6-Pin"
U1: library part MSP430FR698XPZ
U100 U200: "25 MHz Mixed Signal Microcontroller with 128 KB Flash, 8192 B SRAM and 47 GPIOs, -40 to 85 degC, 64-pin QFN (RGC), Green (RoHS & no Sb/Br)"
U400: "Low-Capacitance + / - 15 kV ESD-Protection Array for High-Speed Data Interfaces, 2 Channels, -40 to +85 degC, 5-pin SOT (DRL), Green (RoHS & no Sb/Br)"
U401: "4-Port Full-Speed USB Hub, 3.3V, -40 to 85 degC, 32-Pin QFN (RHB), Green (RoHS & no Sb/Br)"
U402: library part TPS73533DRB, "500mA, Low Quiescent Current, Ultra-Low Noise, High PSRR Low-Dropout Linear Regulator, DRB0008A"
U403: "Buck Step Down Regulator with 2.05 to 6 V Input and 3.3 V Output, -40 to 85 degC, 6-Pin SON (DRY), Green (RoHS & no Sb/Br)"
VR1: library part RPot, "Potentiometer"
X1: library part XTAL3
X2: library part XTAL, "Crystal Oscillator"

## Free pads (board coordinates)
  round 59.06 hole 35.43: 0(150,1650) 0(150,1750) 0(150,2350)
  round 275.59 hole 125.98: 0(200,200) 0(200,4600) 1(3850,200) 1(3850,4600)

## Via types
v1: diameter 31.5, hole 11.81, Top Layer to Bottom Layer, tented both sides, 211 vias
v2: diameter 31.5, hole 11.81, Top Layer to Bottom Layer, tented bottom, 41 vias
v3: diameter 23.81, hole 11.81, Top Layer to Bottom Layer, tented bottom, 5 vias

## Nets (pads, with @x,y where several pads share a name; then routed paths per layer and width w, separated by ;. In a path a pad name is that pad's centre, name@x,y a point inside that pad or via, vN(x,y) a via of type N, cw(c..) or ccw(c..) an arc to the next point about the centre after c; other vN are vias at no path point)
3V3: C102.1 C103.1 C104.1 C202.1 C203.1 C204.1 C205.1 C407.1 C408.1 J401.3 R106.2 R108.2 R209.2 R404.2 R408.2 R419.1 R420.1 R600.1 R601.1 S202.2 U100.11 U100.15 U100.40 U200.11 U200.15 U200.40 U401.3 U401.6 U401.8 U401.10 U401.14 U401.18 U401.22 U401.25 U401.26 | length 2627.5
  Top Layer w8: U100.40@786.84,761.17 786.84,853.22 C104.1@790,856.38 v1(836.38,856.38) ; v1(903.62,213.62) R108.2@903.62,260 ; U100.15@904.95,406.83 904.95,435.05 890,450 840,450 826.21,436.21 U100.11@826.21,406.83 826.21,360.17 C102.1@846.38,340 846.38,313.62 860,300 890,300 903.62,286.38 R108.2@903.62,260 ; C103.1@990,246.18 976.18,260 R108.2@903.62,260 ; v1(1230,620) 1232.24,617.76 U401.22@1287.4,617.76 ; v1(1230,710) 1243.5,696.5 U401.18@1287.4,696.5 ; v1(1240,500) C408.1@1296.38,500 1296.38,516.38 1315.94,535.94 U401.25@1315.94,549.84 U401.26@1335.63,549.84 ; U401.14@1355.32,744.72 v1(1355.32,794.68) ; U401.10@1434.06,744.72 1434.06,764.06 1450,780 1500,780 v1(1520,760) 1520,720 ; U401.3@1482.28,617.76 1657.76,617.76 1670,630 C407.1@1670,656.38 ; U401.6@1482.28,676.81 1506.81,676.81 1520,690 1520,720 ; U401.8@1482.28,716.18 1516.18,716.18 1520,720 ; R404.2@1613.62,650 1663.62,650 C407.1@1670,656.38 ; v1(1716.38,656.38) C407.1@1670,656.38 ; v1(2520,930) S202.2@2573.07,930 ; v1(3126.38,840) 3126.38,843.62 C202.1@3126.38,790 3126.38,743.62 3145.92,724.08 U200.40@3145.92,695.41 ; U200.15@3264.03,341.08 3264.03,365.97 3250,380 3200,380 3185.29,365.29 U200.11@3185.29,341.08 3185.29,293.83 C204.1@3173.62,282.16 v1(3173.62,223.62) 3176.38,226.38 C205.1@3250,226.38 3372.59,226.38 R209.2@3373.19,225.78 ; R601.1@3723.62,1030 3755,1030 ; v1(3755,985) 3755,1030 ; R600.1@3786.38,1030 3755,1030
  Top Layer w10: v1(510,270) R106.2@510,326.38 ; v1(1610,420) R408.2@1651.38,420
  Top Layer w20: R420.1@2153.62,850 2200,850 2201.18,851.18 C203.1@2201.18,930 ; 2200,980 2201.18,978.82
  Top Layer w30: v1(2180,980) 2200,980 v1(2220,980) ; C203.1@2201.18,930 2201.18,978.82
\RF_RESET: PORT_6_8.8 R44.2 U1.62 | length 4559.4
  Top Layer w8: PORT_6_8.8@350,1250 429.6,1250 1179.6,2000 1200,2000 1230,2030 v1(1230,2060) ; v1(490,3400) R44.2@490,3508.5 ; v1(2200,2290) 2230.31,2320.31 U1.62@2425.12,2320.31
  Bottom Layer w8: v1(490,3400) 630.6,3400 1060.76,2969.84 1060.76,2458.84 1192.25,2327.35 1192.25,2258.15 1224.25,2226.15 1224.25,2065.75 v1(1230,2060) 1230,2049.8 1365.8,1914 1924.8,1914 2180,2169.2 2180,2270 v1(2200,2290)
\RF_SPI1_CSN: PORT_2_3.4 R48.2 U1.48 | length 4440.8
  Top Layer w8: R48.2@80,2901.5 v1(80,3140) ; PORT_2_3.4@350,2250 380,2220 870,2220 960,2310 v1(1000,2310) ; v1(2100,1860) 2150,1860 2160,1850 2290,1850 2350,1910 2350,1960 2316.85,1993.15 U1.48@2316.85,2034.88
  Bottom Layer w8: v1(80,3140) 732.21,3140 948.76,2923.45 948.76,2412.44 1000,2361.21 v1(1000,2310) 1000,2230 994.25,2224.25 994.25,2055.14 1247.4,1802 2012,1802 2070,1860 v1(2100,1860)
\RF_SPI_CSN: J601.8 PORT_2_3.8 R54.2 U1.43 | length 5430.8
  Top Layer w8: PORT_2_3.8@350,2050 440,2140 920,2140 970,2190 v1(1020,2190) ; R54.2@440,2901.5 v1(440,3170) ; U1.43@2218.43,2034.88 2218.43,1948.43 2160,1890 v1(2130,1890) 2074,1890 2050,1866 2050,1699.4 2157.4,1592 2437.4,1592 2697.4,1332 2938,1332 J601.8@3050,1220
  Bottom Layer w8: v1(440,3170) 450,3180 712.01,3180 962.76,2929.25 962.76,2418.24 1030,2351.01 1030,2200 v1(1020,2190) 1020,2049.2 1253.2,1816 1996,1816 2070,1890 v1(2130,1890)
AGND: C7.1 C10.1 C11.2 C12.1 C13.2 NT0.1 U1.80 U1.83 U1.86 X1.3
  other v1: 2120,2760 2260,2760 2470,2920 2660,3074
AVCC: C7.2 R65.1 U1.79 | length 317.4
  Top Layer w8: U1.79@2297.17,2645.12 2297.17,2677.17 2426.38,2806.38 C7.2@2470,2806.38
  Top Layer w9.84: C7.2@2470,2806.38 2476.38,2800 R65.1@2526.38,2800
BRIDGE_DM: C201.1 R203.2 U200.52 | length 429.9
  Top Layer w7.87: C201.1@2593.62,620 2670,620 2694.22,595.78 2825.78,595.78 2836.82,606.82 U200.52@2958.92,606.82
  Top Layer w10: C201.1@2593.62,620 R203.2@2593.62,670
BRIDGE_DP: C200.1 R201.2 R206.1 U200.50 | length 406
  Top Layer w7.87: R206.1@2650,723.54 2650,690 2677.84,662.16 2706.17,662.16 ; 2710,663.54 2711.38,662.16 2918.62,662.16 ; 2920,662.16 2935.97,646.19 U200.50@2958.92,646.19
  Top Layer w10: R201.2@2600,726.38 R206.1@2650,726.38
BRIDGE_LED0: R200.2 U200.18 | length 556.8
  Top Layer w7.87: U200.18@3313.25,390.29 3530.29,390.29 3727,587 R200.2@3727,648.54
BRIDGE_LED1: R202.2 U200.19 | length 478.6
  Top Layer w7.87: U200.19@3313.25,409.97 3479.97,409.97 3657,587 R202.2@3657,648.54
BRIDGE_LED2: R204.2 U200.20 | length 406.3
  Top Layer w7.87: U200.20@3313.25,429.66 3439.66,429.66 3587,577 3587,601.16 R204.2@3587,648.54
BRIDGE_LED3: R205.2 U200.21 | length 334
  Top Layer w7.87: U200.21@3313.25,449.34 3399.34,449.34 3517,567 R205.2@3517,648.54
BRIDGE_PUR: R206.2 R210.2 R211.1 U200.51 | length 444.8
  Top Layer w7.87: R206.2@2650,770.78 2809.22,770.78 2820,760 v1(2820,730) ; v1(2820,630) 2823.49,626.51 U200.51@2958.92,626.51
  Bottom Layer w7.87: v1(2820,630) v1(2820,730)
BRIDGE_READY_OUT: J601.5 U200.44 | length 474.2
  Top Layer w8: J601.5@2948,1118 2951.8,1118 3067.18,1002.62 U200.44@3067.18,695.41
BRIDGE_RST: C210.1 J200.1 R209.1 S201.2 U200.64 | length 816.6
  Top Layer w7.87: U200.64@2958.92,370.6 2958.92,241.08 3020,180 3220,180 3250,150 ; J200.1@3250,100 3250,150 ; S201.2@3540,163.07 3476.93,163.07 3461.46,178.54 C210.1@3428.19,178.54 R209.1@3373.19,178.54 3278.54,178.54 3250,150
BRIDGE_TCK: J200.2 U200.63 | length 504.8
  Top Layer w7.87: U200.63@2958.92,390.29 2931.53,390.29 2913.87,372.63 2913.87,196.13 2946.13,163.87 3086.13,163.87 J200.2@3150,100
BRIDGE_TDI: J200.4 U200.61 | length 414.3
  Top Layer w7.87: J200.4@2950,100 2880,170 2880,390 2919.66,429.66 U200.61@2958.92,429.66
BRIDGE_TDO: J200.5 U200.60 | length 417.9
  Top Layer w7.87: J200.5@2850,100 2860,110 2860,390.38 2918.96,449.34 U200.60@2958.92,449.34
BRIDGE_TEST: J200.6 U200.59 | length 478.9
  Top Layer w7.87: J200.6@2750,100 2846.13,196.13 2846.13,396.13 2919.03,469.03 U200.59@2958.92,469.03
BRIDGE_TMS: J200.3 U200.62 | length 448.6
  Top Layer w7.87: U200.62@2958.92,409.97 2929.97,409.97 2900,380 2900,190 2940,150 3000,150 J200.3@3050,100
BRIDGE_UCA0_RXD: J201.3 U200.37 | length 505.4
  Top Layer w8: U200.37@3204.98,695.41 3204.98,725.27 3313.94,834.23 3313.94,1033.94 J201.3@3400,1120
BRIDGE_UCA0_TXD: J201.2 U200.38 | length 472.1
  Top Layer w7.87: U200.38@3185.29,695.41 3185.29,725.29 3300,840 J201.2@3300,1120
BRIDGE_UCA1_RX: J601.1 U200.46 | length 621.7
  Top Layer w8: J601.1@2750,1120 2820,1050 2960,1050 3027.81,982.19 U200.46@3027.81,695.41
BRIDGE_UCA1_TX: J601.3 U200.45 | length 547.4
  Top Layer w8: J601.3@2850,1120 2900,1070 2970,1070 3047.5,992.5 U200.45@3047.5,695.41
BRIDGE_UCB0_DRDY: J600.4 U200.36 | length 621.1
  Top Layer w8: U200.36@3224.66,695.41 3224.66,724.66 3480,980 3550,980 3600,1030 J600.4@3600,1120
BRIDGE_UCB0_SCL: J600.3 R601.2 U200.35 | length 707.2
  Top Layer w7.87: U200.35@3244.35,695.41 3244.35,724.64 3485.77,966.06 3646.06,966.06 3676.38,996.38 3676.38,1020 3676.38,1096.38 J600.3@3700,1120
BRIDGE_UCB0_SDA: J600.2 R600.2 U200.34 | length 850.6
  Top Layer w7.87: U200.34@3264.03,695.41 3264.03,724.7 3491.52,952.19 3792.19,952.19 3833.62,993.62 3833.62,1020 3833.62,1086.38 J600.2@3800,1120
BRIDGE_V18: C207.1 U200.55 | length 189.2
  Top Layer w7.87: C207.1@2793.62,490 2837.84,490 2895.61,547.77 U200.55@2958.92,547.77
BRIDGE_VCORE: C208.1 U200.17 | length 65.3
  Top Layer w7.87: U200.17@3313.25,370.6 3366.56,370.6 3375,362.16
BRIDGE_VUSB: C206.1 U200.54 | length 176.7
  Top Layer w7.87: C206.1@2793.62,540 2860,540 2887.45,567.45 U200.54@2958.92,567.45
BRIDGE_XT2IN: Q200.1 U200.57 | length 389.7
  Top Layer w7.87: Q200.1@2680,340 2680,410 2710,440 2820,440 2888.4,508.4 U200.57@2958.92,508.4
BRIDGE_XT2OUT: Q200.3 U200.58 | length 255.7
  Top Layer w7.87: Q200.3@2800,340 2800,400 2888.71,488.71 U200.58@2958.92,488.71
BUCK_3V3: C417.1 L400.2 R420.2 U403.6 | length 443.6
  Top Layer w10: L400.2@1864,736.61 1865.53,735.08 1950.08,735.08 1985,700.16 U403.6@1985,670 2009.53,670 2029.53,690 C417.1@2085.13,690
  Top Layer w20: C417.1@2085.13,690 2085.13,769.87 2085,770 2085,795 2106.38,816.38 R420.2@2106.38,850
BUT_AIN: BUT.6 C36.1 R3.1 R5.2 U1.64 | length 1034.8
  Top Layer w8: U1.64@2425.12,2359.68 2489.68,2359.68 v1(2500,2370) ; v1(2610,2350) 2931.5,2028.5 R5.2@3100,2028.5 ; R3.1@3030,1961.49 3097.01,1961.49 3098.5,1960 3100,1961.5 R5.2@3100,2028.5 ; BUT.6@3174.8,2031.18 3102.68,2031.18 R5.2@3100,2028.5
  Bottom Layer w8: v1(2500,2370) 2590,2370 v1(2610,2350)
BUT_AIN2: BUT.7 R5.1 R6.2 | length 263.4
  Top Layer w10: R5.1@3100,2091.49 3168.19,2091.49 BUT.7@3174.8,2098.11 3216.61,2098.11 R6.2@3318.5,2200
BUT_AIN3: BUT.5 R6.1 R7.2 | length 267.6
  Top Layer w10: R6.1@3381.49,2200 3483.38,2098.11 BUT.5@3525.2,2098.11 3583.39,2098.11 R7.2@3600,2081.5
BUT_AIN4: BUT.3 R7.1 R8.2 | length 162.9
  Top Layer w10: BUT.3@3525.2,1928.82 3597.32,1928.82 3600,1931.5 R7.1@3600,2018.51
BUT_AIN5: BUT.4 R8.1 | length 77.5
  Top Layer w10: BUT.4@3525.2,1861.89 3531.81,1868.51 R8.1@3600,1868.51
COM0: LCD.28 U1.10 | length 3586.6
  Top Layer w8: v1(1480,2440) 1586.01,2440 1626.96,2399.06 U1.10@1814.88,2399.06
  Bottom Layer w8: v1(1480,2440) 1459.31,2440 1330,2569.31 1330,3078.99 1400,3148.99 1400,4260 1530,4390 2290,4390 LCD.28@2550,4650
COM1: LCD.27 U1.11 | length 3606.6
  Top Layer w8: v1(1520,2410) 1596.21,2410 1626.84,2379.37 U1.11@1814.88,2379.37
  Bottom Layer w8: v1(1520,2410) 1520,2440 1344,2616 1344,3073.2 1500,3229.2 1500,4260 1616,4376 2376,4376 LCD.27@2650,4650
COM2: LCD.26 U1.12 | length 3638.7
  Top Layer w8: v1(1560,2380) 1606.41,2380 1626.73,2359.69 U1.12@1814.88,2359.69
  Bottom Layer w8: v1(1560,2380) 1560,2420 1358,2622 1358,3067.4 1600,3309.4 1600,4260 1702,4362 2462,4362 LCD.26@2750,4650
COM3: LCD.25 U1.13 | length 3670.9
  Top Layer w8: v1(1600,2350) 1610,2350 1620,2340 U1.13@1814.88,2340
  Bottom Layer w8: v1(1600,2350) 1600,2400 1372,2628 1372,3061.6 1700,3389.6 1700,4260 1788,4348 2548,4348 LCD.25@2850,4650
D+: J400.3 R407.1 U400.5 | length 285.9
  Top Layer w7.87: R407.1@1811.81,420 1811.81,348.19 1865,295 U400.5@1912.87,295 1914.45,293.42 J400.3@1914.45,214.68 J400.3@1914.45,204.68
D-: J400.2 R409.1 U400.3 | length 435
  Top Layer w7.87: R409.1@1812.81,524 1812.81,502.19 1855,460 1908,460 1966.02,401.98 U400.3@1966.02,334.37 1949.13,334.37 1939.45,324.68 1940.04,324.09 J400.2@1940.04,204.68
DM0: C404.1 R409.2 U401.2 | length 372.4
  Top Layer w7.87: U401.2@1482.28,598.07 1528.74,598.07 1601.81,525 1754.57,525 1765.57,536 ; R409.2@1765.57,524 1765.57,577.19 C404.1@1766.38,578
DM1: C412.1 R417.2 U401.11 | length 268.9
  Top Layer w7.87: U401.11@1414.37,744.72 1414.37,859.37 1460,905 1460,928.54 1463.15,931.69 1471.5,923.35 C412.1@1521.38,923.35
DM2: C406.1 R413.2 U401.15 | length 301.2
  Top Layer w7.87: C406.1@1265,1011.38 1265,980 1258.62,973.62 1258.62,846.38 1335.63,769.37 U401.15@1335.63,744.72
DM3: R401.2 U401.19 | length 154.4
  Top Layer w7.87: R401.2@1143.46,701.97 1168.03,701.97 1193.19,676.81 U401.19@1287.4,676.81
DM4: R403.2 U401.23 | length 165.1
  Top Layer w7.87: R403.2@1143.46,576.97 1169.84,576.97 1184.84,561.97 1229.84,561.97 1265.94,598.07 U401.23@1287.4,598.07
DP0: C403.1 R407.2 R408.1 U401.1 | length 491.5
  Top Layer w7.87: U401.1@1482.28,578.39 1518.43,578.39 1611.81,485 1735,485 1765,455 1765,420.43 R407.2@1764.57,420 R408.1@1698.62,420
  Top Layer w10: R407.2@1764.57,420 1764.57,364.06 C403.1@1765,363.62
DP1: C410.1 R416.2 U401.12 | length 295.1
  Top Layer w7.87: C410.1@1326,1011.38 1326,980 1336.88,969.12 R416.2@1336.88,950 1336.88,934.93 1394.69,877.13 U401.12@1394.69,744.72
DP2: C405.1 R412.2 U401.16 | length 220.1
  Top Layer w7.87: C405.1@1147.96,830 1185,830 1191.38,836.38 R412.2@1211.31,836.38 1244.02,836.38 1315.94,764.45 U401.16@1315.94,744.72
DP3: R400.2 U401.20 | length 152.2
  Top Layer w7.87: R400.2@1143.46,646.97 1169.84,646.97 1184.84,661.97 1244.84,661.97 1249.69,657.13 U401.20@1287.4,657.13
DP4: R402.2 U401.24 | length 167.3
  Top Layer w7.87: R402.2@1143.46,521.97 1214.84,521.97 1271.26,578.39 U401.24@1287.4,578.39
ESICH0/ESITEST0: ESI.14 PORT_9/ESI.14 U1.67 | length 1979.3
  Top Layer w8: U1.67@2425.12,2418.74 2866.73,2418.74 3300,2852.01 3300,2852.21 3304,2856.21 3304,3094 3360,3150 3500,3150 PORT_9/ESI.14@3550,3200
  Bottom Layer w8: PORT_9/ESI.14@3550,3200 3650,3200 3700,3250 3850,3250 ESI.14@3900,3200
ESICH1/ESITEST1: ESI.13 PORT_9/ESI.13 U1.68 | length 1888.9
  Top Layer w8: U1.68@2425.12,2438.43 2866.62,2438.43 3286,2857.81 3286,2858.01 3290,2862.01 3290,3130 3360,3200 PORT_9/ESI.13@3450,3200
  Bottom Layer w8: PORT_9/ESI.13@3450,3200 3500,3150 3650,3150 3700,3200 ESI.13@3800,3200
ESICH2/ESITEST2: ESI.12 PORT_9/ESI.12 U1.69 | length 2039.8
  Top Layer w8: U1.69@2425.12,2458.11 2866.5,2458.11 3272,2863.61 3272,2863.81 3276,2867.81 3276,3166 3360,3250 3500,3250 PORT_9/ESI.12@3550,3300
  Bottom Layer w8: PORT_9/ESI.12@3550,3300 3650,3300 3700,3350 3850,3350 ESI.12@3900,3300
ESICH3/ESITEST3: ESI.11 PORT_9/ESI.11 U1.70 | length 1949.4
  Top Layer w8: U1.70@2425.12,2477.8 2866.39,2477.8 3258,2869.41 3258,2869.61 3262,2873.61 3262,3202 3360,3300 PORT_9/ESI.11@3450,3300
  Bottom Layer w8: PORT_9/ESI.11@3450,3300 3500,3250 3650,3250 3700,3300 ESI.11@3800,3300
ESICI: ESI.6 PORT_9/ESI.6 U1.77 | length 2362.7
  Top Layer w8: U1.77@2336.54,2645.12 2336.54,2676.54 2356,2696 2434,2696 v1(2450,2680) ; v1(2740,2620) 2909.6,2620 3188,2898.4 3188,2898.6 3192,2902.6 3192,3382 3360,3550 3500,3550 PORT_9/ESI.6@3550,3600
  Bottom Layer w8: v1(2450,2680) 2510,2620 v1(2740,2620) ; PORT_9/ESI.6@3550,3600 3650,3600 3700,3650 3850,3650 ESI.6@3900,3600
ESICI0: ESI.10 PORT_9/ESI.10 U1.71 | length 2100.3
  Top Layer w8: U1.71@2425.12,2497.48 2866.27,2497.48 3244,2875.21 3244,2875.41 3248,2879.41 3248,3238 3360,3350 3500,3350 PORT_9/ESI.10@3550,3400
  Bottom Layer w8: PORT_9/ESI.10@3550,3400 3650,3400 3700,3450 3850,3450 ESI.10@3900,3400
ESICI1: ESI.9 PORT_9/ESI.9 U1.72 | length 2009.9
  Top Layer w8: U1.72@2425.12,2517.17 2866.16,2517.17 3230,2881.01 3230,2881.21 3234,2885.21 3234,3274 3360,3400 PORT_9/ESI.9@3450,3400
  Bottom Layer w8: PORT_9/ESI.9@3450,3400 3500,3350 3650,3350 3700,3400 ESI.9@3800,3400
ESICI2: ESI.8 PORT_9/ESI.8 U1.73 | length 2160.8
  Top Layer w8: U1.73@2425.12,2536.85 2866.05,2536.85 3216,2886.8 3216,2887.01 3220,2891.01 3220,3310 3360,3450 3500,3450 PORT_9/ESI.8@3550,3500
  Bottom Layer w8: PORT_9/ESI.8@3550,3500 3650,3500 3700,3550 3850,3550 ESI.8@3900,3500
ESICI3: ESI.7 PORT_9/ESI.7 U1.74 | length 2070.3
  Top Layer w8: U1.74@2425.12,2556.54 2865.93,2556.54 3202,2892.6 3202,2892.8 3206,2896.8 3206,3346 3360,3500 PORT_9/ESI.7@3450,3500
  Bottom Layer w8: PORT_9/ESI.7@3450,3500 3500,3450 3650,3450 3700,3500 ESI.7@3800,3500
ESICOM: C34.1 ESI.5 PORT_9/ESI.5 U1.78 | length 2779.2
  Top Layer w8: U1.78@2316.85,2645.12 2316.85,2676.85 2350,2710 C34.1@2496.38,2710 2496.38,2726.38 2530,2760 2990,2760 3150,2920 3150,3540 3360,3750 3580,3750 3610,3720 3610,3680 3580,3650 3520,3650 3470,3600 PORT_9/ESI.5@3450,3600
  Bottom Layer w8: PORT_9/ESI.5@3450,3600 3500,3550 3650,3550 3700,3600 ESI.5@3800,3600
ESITEST4: ESI.16 PORT_9/ESI.16 U1.63 | length 1923.5
  Top Layer w8: U1.63@2425.12,2340 2520.94,2340 2580.94,2400 2867.79,2400 3320,2852.21 3320,3010 3360,3050 3500,3050 PORT_9/ESI.16@3550,3100
  Bottom Layer w8: PORT_9/ESI.16@3550,3100 3650,3100 3700,3150 3850,3150 ESI.16@3900,3100
ESIVCC: C35.2 ESI.4 PORT_9/ESI.4 U1.75 | length 2323
  Top Layer w8: U1.75@2425.12,2576.22 2606.22,2576.22 2653.62,2623.62 C35.2@2653.62,2647.88 ; C35.2@2653.62,2650 2919.8,2650 3174,2904.2 3174,2904.4 3178,2908.4 3178,3468 3360,3650 3470,3650 3520,3700 PORT_9/ESI.4@3550,3700
  Bottom Layer w8: PORT_9/ESI.4@3550,3700 3650,3700 3700,3750 3850,3750 ESI.4@3900,3700
ESIVSS: C34.2 C35.1 ESI.3 PORT_9/ESI.3 R63.2 U1.76 | length 2375.3
  Top Layer w8: U1.76@2356.22,2645.12 2601.5,2645.12 C35.1@2606.38,2650 R63.2@2606.38,2710 ; C34.2@2543.62,2710 R63.2@2606.38,2710 ; PORT_9/ESI.3@3450,3700 3360,3700 3164,3504 3164,2914.2 3160,2910.2 3160,2910 3000,2750 2999.8,2750 2995.8,2746 2626,2746 2606.38,2726.38 R63.2@2606.38,2710
  Bottom Layer w8: PORT_9/ESI.3@3450,3700 3500,3650 3650,3650 3700,3700 ESI.3@3800,3700
EZFET_AVBUS: C110.1 R109.2 R110.1 U100.1 | length 263.4
  Top Layer w7.87: R109.2@570,258.62 C110.1@625,258.62 ; C110.1@627.36,260.98 C110.1@625,258.62 ; U100.1@629.36,406.83 629.36,262.98 C110.1@625,258.62 ; R110.1@680,258.62 C110.1@625,258.62
EZFET_AVCCOUT2ADC: C109.1 R107.2 R108.1 U100.2 | length 334.5
  Top Layer w7.87: U100.2@649.05,406.83 649.05,320.95 670,300 720,300 735,285 C109.1@735,258.62 R107.2@790,258.62 R108.1@856.38,258.62
EZFET_DM: C101.1 R101.2 U100.52 | length 506.9
  Top Layer w7.87: C101.1@596.38,1065 R101.2@596.38,1010 575,1010 505,940 505,725 557.42,672.58 U100.52@599.83,672.58
EZFET_DP: C100.1 R100.2 R102.1 R103.2 U100.50 | length 334.7
  Top Layer w7.87: C100.1@596.38,835.5 566.38,805.5 566.38,723.62 578.05,711.95 U100.50@599.83,711.95
  Top Layer w10: R103.2@535,888.62 536.88,890.5 R102.1@596.38,890.5 ; C100.1@596.38,835.5 R102.1@596.38,890.5 ; R100.2@596.38,945.5 R102.1@596.38,890.5
EZFET_LED0: R104.2 U100.20 | length 292.9
  Top Layer w7.87: U100.20@954.16,495.42 1009.58,495.42 1066,439 R104.2@1066,281.32
EZFET_LED1: R105.2 U100.21 | length 346
  Top Layer w7.87: U100.21@954.16,515.1 1009.9,515.1 1010,515 1020,515 1132,403 R105.2@1132,281.32
EZFET_PUR: R103.1 U100.51 | length 194.8
  Top Layer w7.87: R103.1@535,841.38 535,725 567.73,692.27 U100.51@599.83,692.27
EZFET_RST: C111.1 J100.1 R106.1 U100.64 | length 574.8
  Top Layer w7.87: J100.1@100,450 280,450 356.38,373.62 C111.1@460,373.62 R106.1@510,373.62 566.62,373.62 599.83,406.83 U100.64@599.83,436.36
